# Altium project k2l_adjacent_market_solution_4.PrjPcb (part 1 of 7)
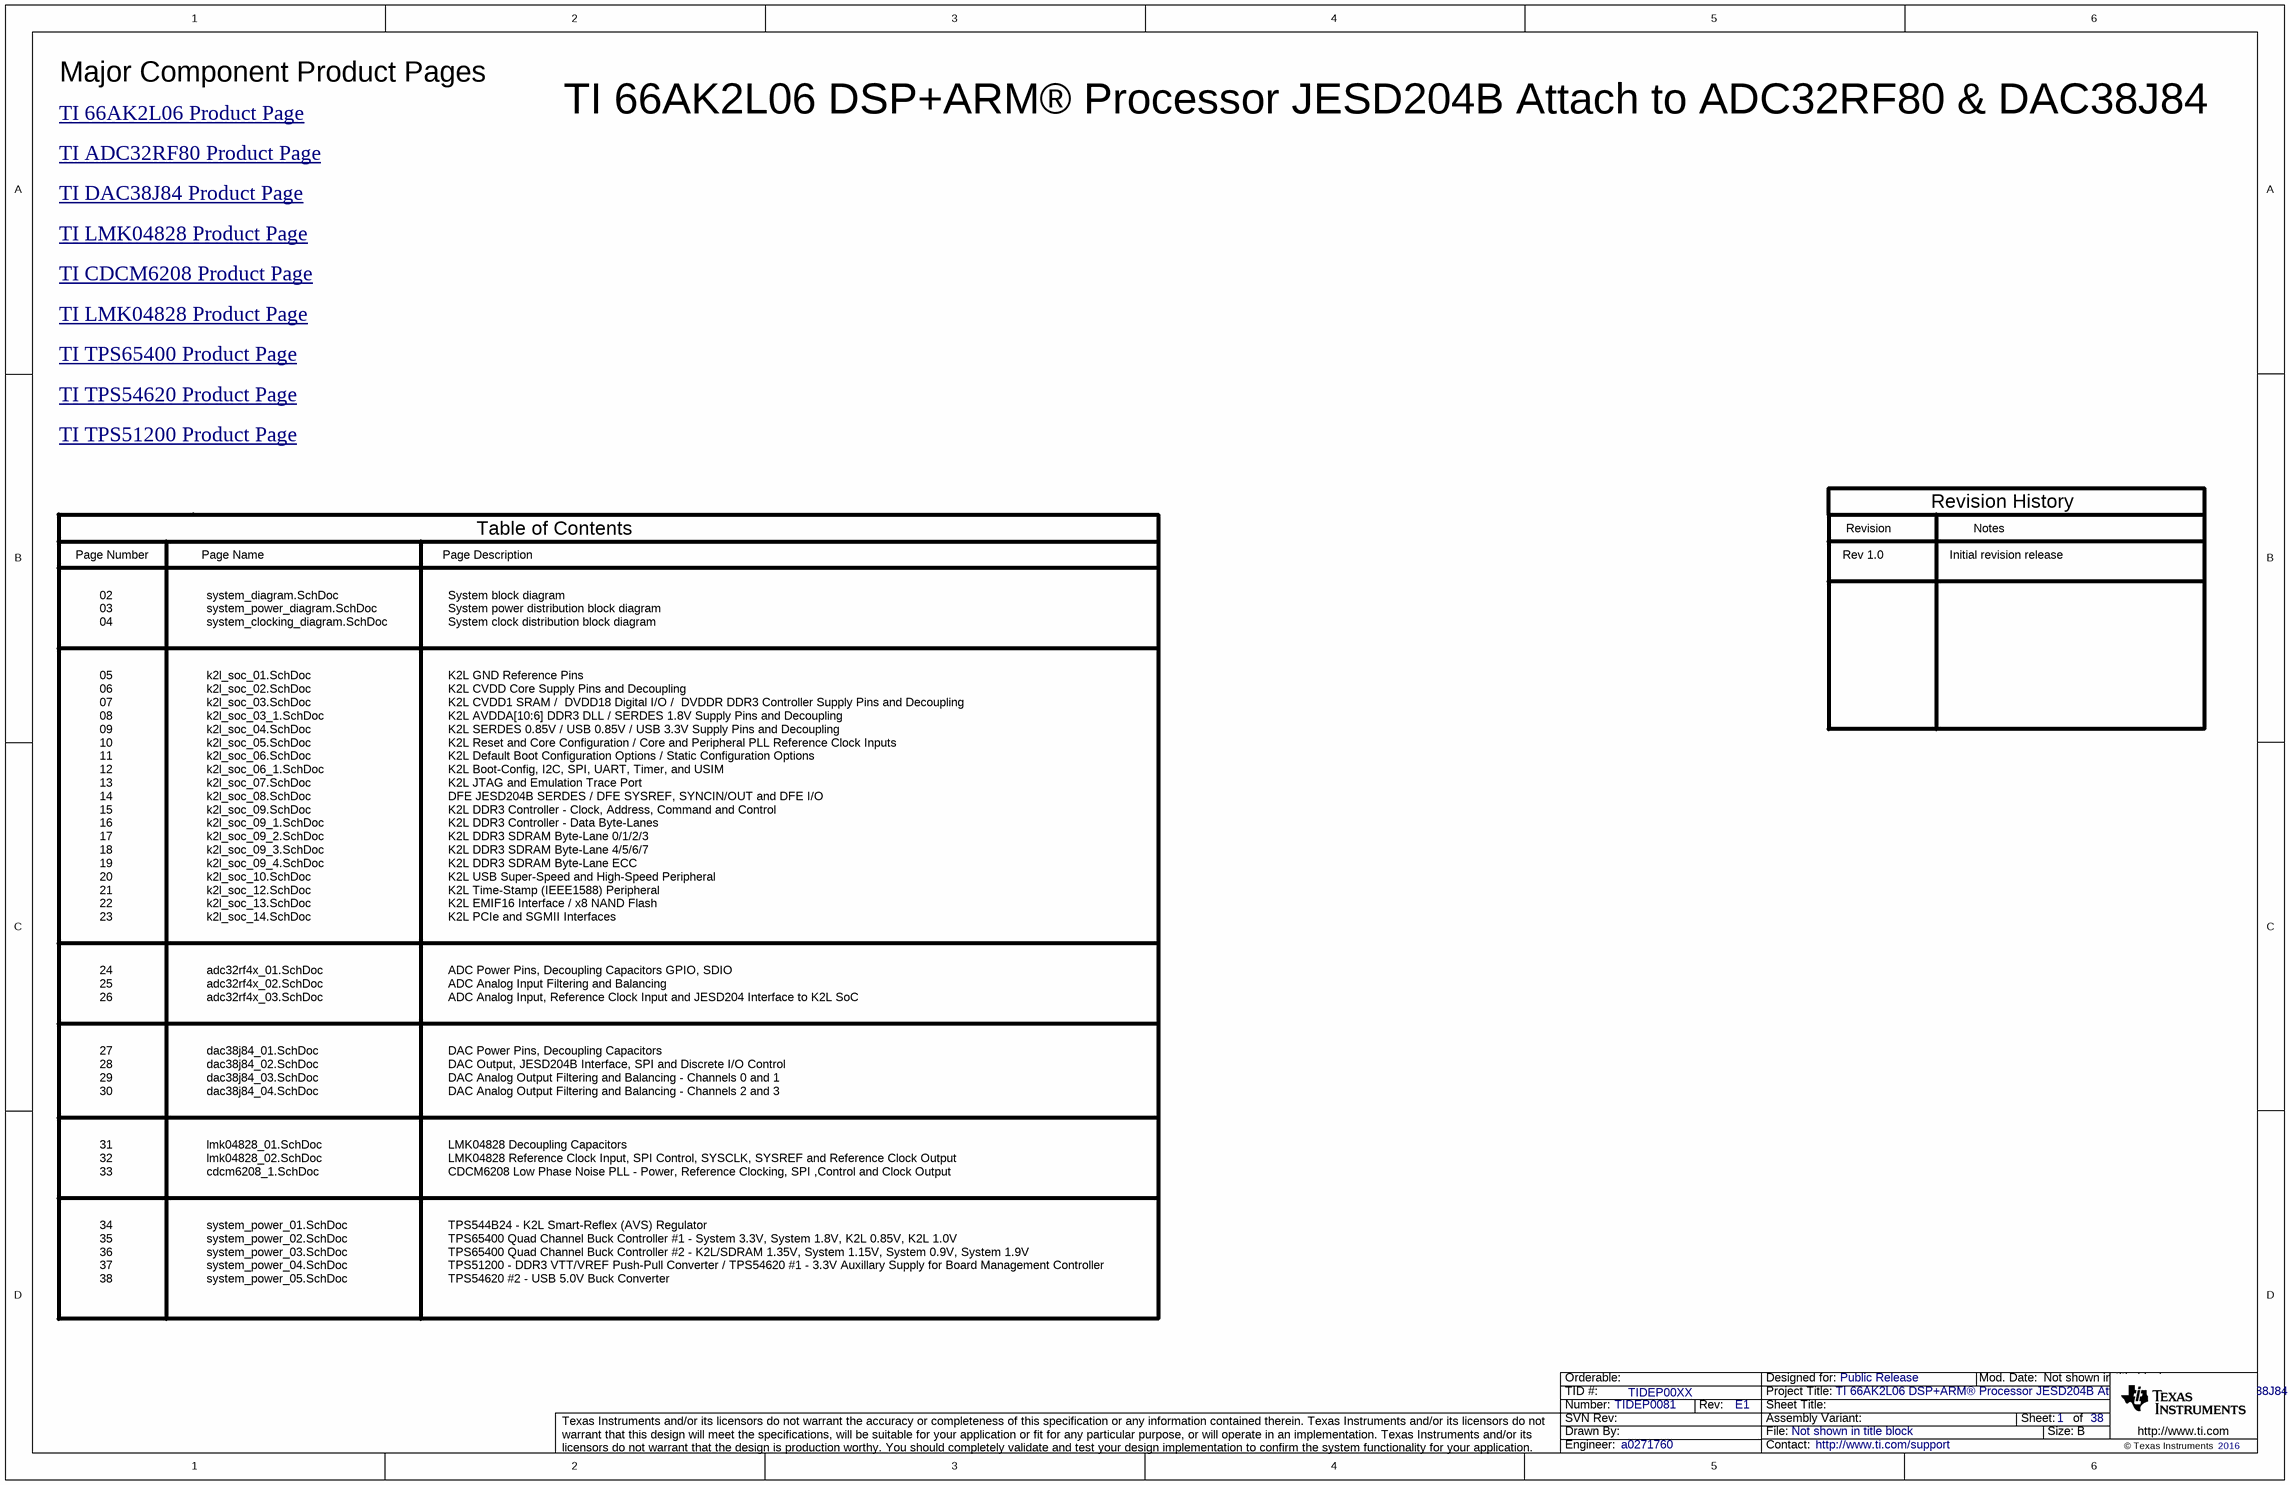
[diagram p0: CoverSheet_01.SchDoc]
TID: TIDEP00XX; TechSupport: http://www.ti.com/support; SCH_Rev: E1; PRJ_Title: TI 66AK2L06 DSP+ARM® Processor JESD204B Attach to ADC32RF80 & DAC38J84; PRJ_Number: TIDEP0081; PRJ_Engineer: a0271760; PRJ_Customer: Public Release; PCB_Rev: E1; PCB_Layout: N/A; CopyrightYear: 2016
38 sheets, 1280 parts. Net scope: flat (ports and power ports of the same name join across sheets).
Sheets:
  CoverSheet_01.SchDoc
  system_diagram.SchDoc
  system_power_diagram.SchDoc
  system_clocking_diagram.SchDoc
  k2l_soc_01.SchDoc
  k2l_soc_02.SchDoc
  k2l_soc_03.SchDoc
  k2l_soc_03_1.SchDoc
  k2l_soc_04.SchDoc
  k2l_soc_05.SchDoc
  k2l_soc_06.SchDoc
  k2l_soc_06_1.SchDoc
  k2l_soc_07.SchDoc
  k2l_soc_08.SchDoc
  k2l_soc_09.SchDoc
  k2l_soc_09_1.SchDoc
  k2l_soc_09_2.SchDoc
  k2l_soc_09_3.SchDoc
  k2l_soc_09_4.SchDoc
  k2l_soc_10.SchDoc
  k2l_soc_12.SchDoc
  k2l_soc_13.SchDoc
  k2l_soc_14.SchDoc
  adc32rf4x_01.SchDoc
  adc32rf4x_02.SchDoc
  adc32rf4x_03.SchDoc
  dac38j84_01.SchDoc
  dac38j84_02.SchDoc
  dac38j84_03.SchDoc
  dac38j84_04.SchDoc
  lmk04828_01.SchDoc
  lmk04828_02.SchDoc
  cdcm6208_1.SchDoc
  system_power_01.SchDoc
  system_power_02.SchDoc
  system_power_03.SchDoc
  system_power_04.SchDoc
  system_power_05.SchDoc

## Sheet CoverSheet_01.SchDoc
size 431 x 279 mm; Date: Not shown in title block; ApprovedBy: Not shown in title block; CheckedBy: Not shown in title block; Author: Not shown in title block; CompanyName: Not shown in title block; Engineer: Not shown in title block; Organization: Not shown in title block; Address1: Not shown in title block; Address2: Not shown in title block; Address3: Not shown in title block; Address4: Not shown in title block; DocumentNumber: 1; Revision: Use project parameter SCH_Rev; SheetNumber: 1; SheetTotal: 38; PageSetup: Record=PageOptions¦CenterHorizontal=True¦CenterVertical=True¦PrintScale=1.00¦XCorrection=1.00¦YCorrection=1.00¦PrintKind=0¦BorderSize=5000000¦LeftOffset=0¦BottomOffset=0¦Orientation=2¦PaperLength=1000¦PaperWidth=1000¦Scale=100¦PaperSource=15¦PrintQuality=600¦MediaType=1¦DitherType=10¦PaperKind=Letter¦PrintScaleMode=1

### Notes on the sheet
- Major Component Product Pages
- TI 66AK2L06 DSP+ARM® Processor JESD204B Attach to ADC32RF80 & DAC38J84
- TI 66AK2L06 Product Page <http://www.ti.com/lsds/ti/dsp/keystone_arm/66ak2lx/overview.page>
- TI ADC32RF80 Product Page <http://www.ti.com/product/ADC32RF80/description>
- TI DAC38J84 Product Page <http://www.ti.com/product/DAC38J84/description>
- TI CDCM6208 Product Page <http://www.ti.com/product/cdcm6208>
- TI LMK04828 Product Page <http://www.ti.com/product/lmk04828>
- TI TPS65400 Product Page <http://www.ti.com/product/TPS65400>
- TI TPS54620 Product Page <http://www.ti.com/product/TPS54620>
- TI TPS51200 Product Page <http://www.ti.com/product/TPS51200>
- Revision History
- Page Number
- Page Name
- Page Description
- Table of Contents
- Rev 1.0
- Revision
- Initial revision release
- Notes
- 02
- 03
- 04
- system_diagram.SchDoc
- system_power_diagram.SchDoc
- system_clocking_diagram.SchDoc
- System block diagram
- System power distribution block diagram
- System clock distribution block diagram
- 05
- 06
- 07
- k2l_soc_01.SchDoc
- k2l_soc_02.SchDoc
- k2l_soc_03.SchDoc
- K2L GND Reference Pins
- K2L CVDD Core Supply Pins and Decoupling
- K2L CVDD1 SRAM /  DVDD18 Digital I/O /  DVDDR DDR3 Controller Supply Pins and Decoupling
- 08
- 09
- 10
- 11
- 12
- k2l_soc_03_1.SchDoc
- k2l_soc_04.SchDoc
- k2l_soc_05.SchDoc
- k2l_soc_06.SchDoc
- k2l_soc_06_1.SchDoc
- K2L AVDDA[10:6] DDR3 DLL / SERDES 1.8V Supply Pins and Decoupling
- K2L SERDES 0.85V / USB 0.85V / USB 3.3V Supply Pins and Decoupling
- K2L Reset and Core Configuration / Core and Peripheral PLL Reference Clock Inputs
- K2L Default Boot Configuration Options / Static Configuration Options
- K2L Boot-Config, I2C, SPI, UART, Timer, and USIM
- 13
- 14
- 15
- 16
- 17
- k2l_soc_07.SchDoc
- k2l_soc_08.SchDoc
- k2l_soc_09.SchDoc
- k2l_soc_09_1.SchDoc
- k2l_soc_09_2.SchDoc
- K2L JTAG and Emulation Trace Port
- DFE JESD204B SERDES / DFE SYSREF, SYNCIN/OUT and DFE I/O
- K2L DDR3 Controller - Clock, Address, Command and Control
- K2L DDR3 Controller - Data Byte-Lanes
- K2L DDR3 SDRAM Byte-Lane 0/1/2/3
- 18
- 19
- 20
- 21
- 22
- k2l_soc_09_3.SchDoc
- k2l_soc_09_4.SchDoc
- k2l_soc_10.SchDoc
- k2l_soc_12.SchDoc
- k2l_soc_13.SchDoc
- K2L DDR3 SDRAM Byte-Lane 4/5/6/7
- K2L DDR3 SDRAM Byte-Lane ECC
- K2L USB Super-Speed and High-Speed Peripheral
- K2L Time-Stamp (IEEE1588) Peripheral
- K2L EMIF16 Interface / x8 NAND Flash
- 23
- 24
- k2l_soc_14.SchDoc
- adc32rf4x_01.SchDoc
- K2L PCIe and SGMII Interfaces
- ADC Power Pins, Decoupling Capacitors GPIO, SDIO
- 25
- 26
- adc32rf4x_02.SchDoc
- adc32rf4x_03.SchDoc
- ADC Analog Input Filtering and Balancing
- ADC Analog Input, Reference Clock Input and JESD204 Interface to K2L SoC
- 27
- 28
- 29
- 30
- dac38j84_01.SchDoc
- dac38j84_02.SchDoc
- dac38j84_03.SchDoc
- dac38j84_04.SchDoc
- DAC Power Pins, Decoupling Capacitors
- DAC Output, JESD204B Interface, SPI and Discrete I/O Control
- DAC Analog Output Filtering and Balancing - Channels 0 and 1
- DAC Analog Output Filtering and Balancing - Channels 2 and 3
- 31
- 32
- 33
- lmk04828_01.SchDoc
- lmk04828_02.SchDoc
- cdcm6208_1.SchDoc
- LMK04828 Decoupling Capacitors
- LMK04828 Reference Clock Input, SPI Control, SYSCLK, SYSREF and Reference Clock Output
- CDCM6208 Low Phase Noise PLL - Power, Reference Clocking, SPI ,Control and Clock Output
- 34
- 35
- system_power_01.SchDoc
- system_power_02.SchDoc
- TPS544B24 - K2L Smart-Reflex (AVS) Regulator
- TPS65400 Quad Channel Buck Controller #1 - System 3.3V, System 1.8V, K2L 0.85V, K2L 1.0V
- 36
- 37
- 38
- system_power_03.SchDoc
- system_power_04.SchDoc
- system_power_05.SchDoc
- TPS65400 Quad Channel Buck Controller #2 - K2L/SDRAM 1.35V, System 1.15V, System 0.9V, System 1.9V
- TPS51200 - DDR3 VTT/VREF Push-Pull Converter / TPS54620 #1 - 3.3V Auxillary Supply for Board Management Controller
- TPS54620 #2 - USB 5.0V Buck Converter

## Sheet system_diagram.SchDoc
size 431 x 279 mm; Date: Not shown in title block; ApprovedBy: Not shown in title block; CheckedBy: Not shown in title block; Author: Not shown in title block; CompanyName: Not shown in title block; DrawnBy: a0271760; Engineer: a0271760; Organization: Not shown in title block; Address1: Not shown in title block; Address2: Not shown in title block; Address3: Not shown in title block; Address4: Not shown in title block; DocumentNumber: 2; Revision: Use project parameter SCH_Rev; SheetNumber: 2; SheetTotal: 38; PageSetup: Record=PageOptions¦CenterHorizontal=True¦CenterVertical=True¦PrintScale=1.00¦XCorrection=1.00¦YCorrection=1.00¦PrintKind=0¦BorderSize=5000000¦LeftOffset=0¦BottomOffset=0¦Orientation=2¦PaperLength=1000¦PaperWidth=1000¦Scale=100¦PaperSource=15¦PrintQuality=600¦MediaType=1¦DitherType=10¦PaperKind=Letter¦PrintScaleMode=1
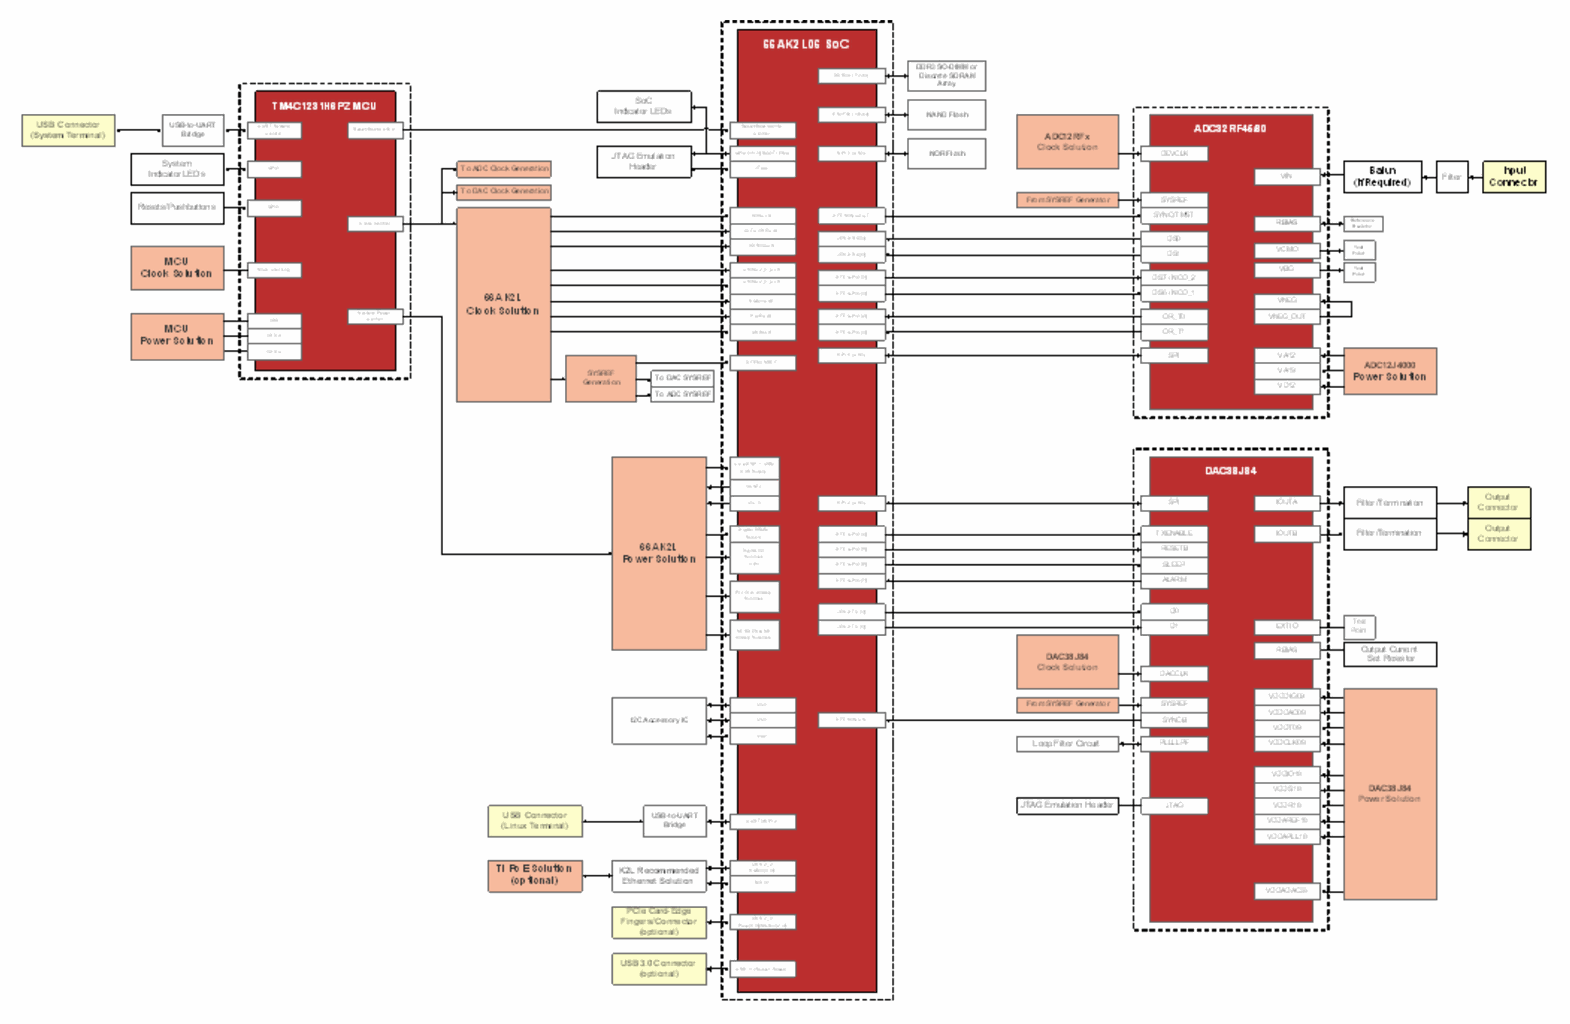
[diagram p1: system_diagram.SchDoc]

## Sheet system_power_diagram.SchDoc
size 431 x 279 mm; Date: Not shown in title block; ApprovedBy: Not shown in title block; CheckedBy: Not shown in title block; Author: Not shown in title block; CompanyName: Not shown in title block; Engineer: Not shown in title block; Organization: Not shown in title block; Address1: Not shown in title block; Address2: Not shown in title block; Address3: Not shown in title block; Address4: Not shown in title block; DocumentNumber: 3; Revision: Use project parameter SCH_Rev; SheetNumber: 3; SheetTotal: 38; PageSetup: Record=PageOptions¦CenterHorizontal=True¦CenterVertical=True¦PrintScale=1.00¦XCorrection=1.00¦YCorrection=1.00¦PrintKind=0¦BorderSize=5000000¦LeftOffset=0¦BottomOffset=0¦Orientation=2¦PaperLength=1000¦PaperWidth=1000¦Scale=100¦PaperSource=15¦PrintQuality=600¦MediaType=1¦DitherType=10¦PaperKind=Letter¦PrintScaleMode=1
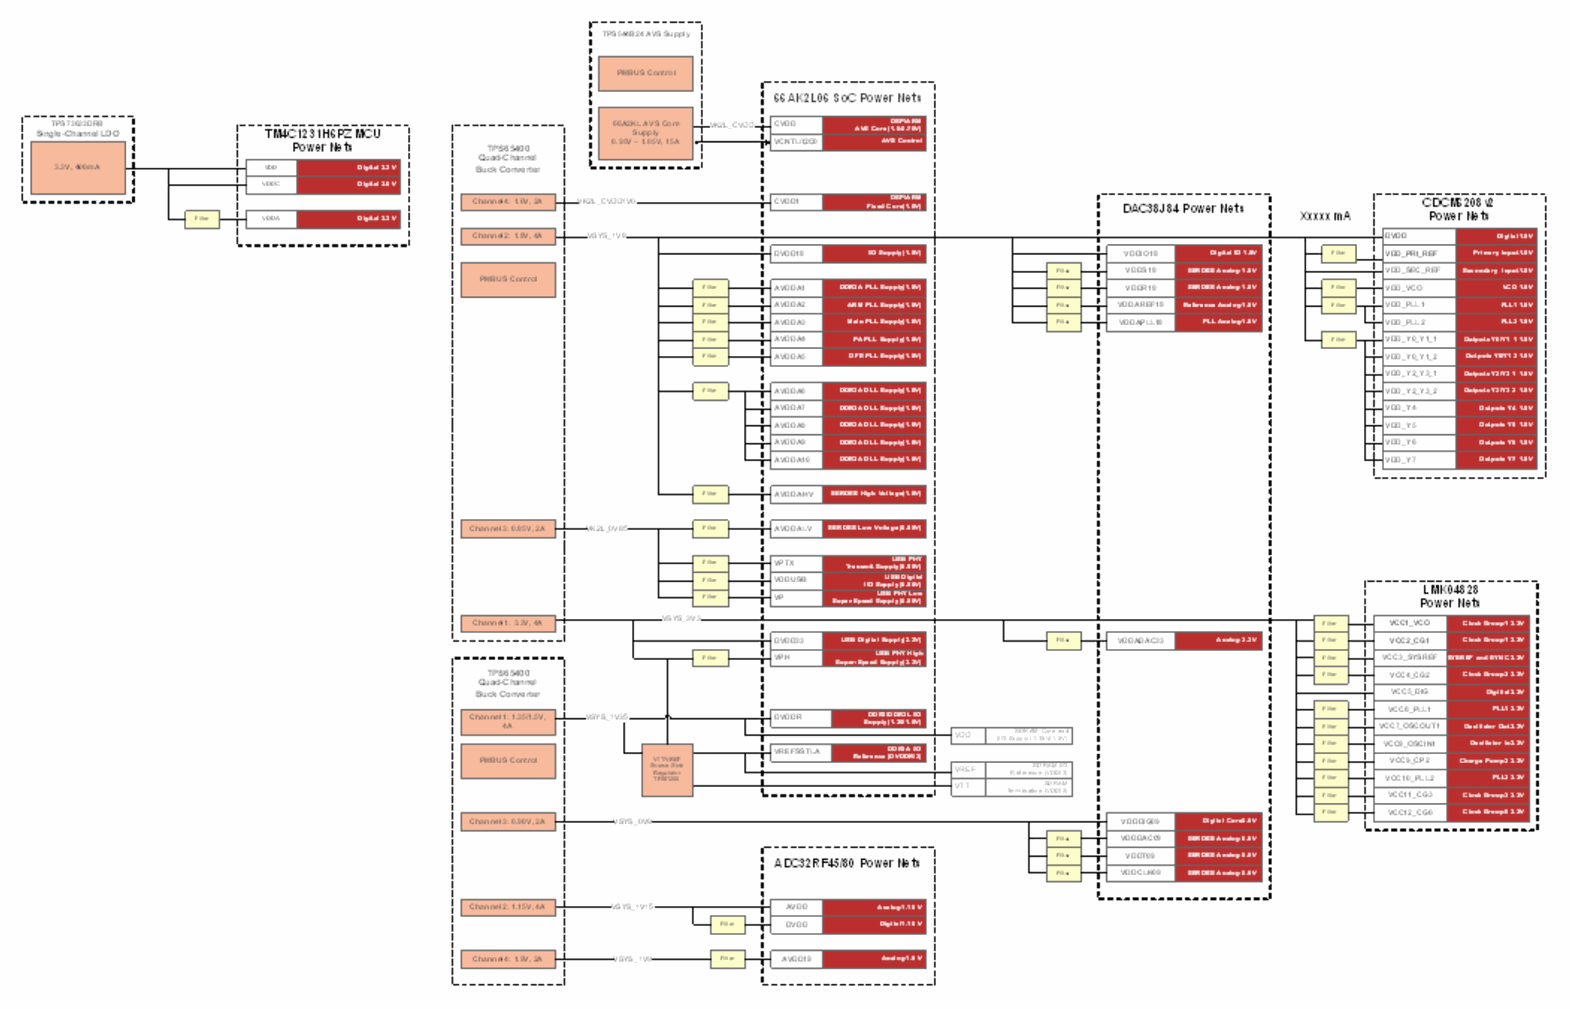
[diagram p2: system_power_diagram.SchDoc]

## Sheet system_clocking_diagram.SchDoc
size 431 x 279 mm; Date: Not shown in title block; ApprovedBy: Not shown in title block; CheckedBy: Not shown in title block; Author: Not shown in title block; CompanyName: Not shown in title block; Engineer: Not shown in title block; Organization: Not shown in title block; Address1: Not shown in title block; Address2: Not shown in title block; Address3: Not shown in title block; Address4: Not shown in title block; DocumentNumber: 4; Revision: Use project parameter SCH_Rev; SheetNumber: 4; SheetTotal: 38; PageSetup: Record=PageOptions¦CenterHorizontal=True¦CenterVertical=True¦PrintScale=1.00¦XCorrection=1.00¦YCorrection=1.00¦PrintKind=0¦BorderSize=5000000¦LeftOffset=0¦BottomOffset=0¦Orientation=2¦PaperLength=1000¦PaperWidth=1000¦Scale=100¦PaperSource=15¦PrintQuality=600¦MediaType=1¦DitherType=10¦PaperKind=Letter¦PrintScaleMode=1
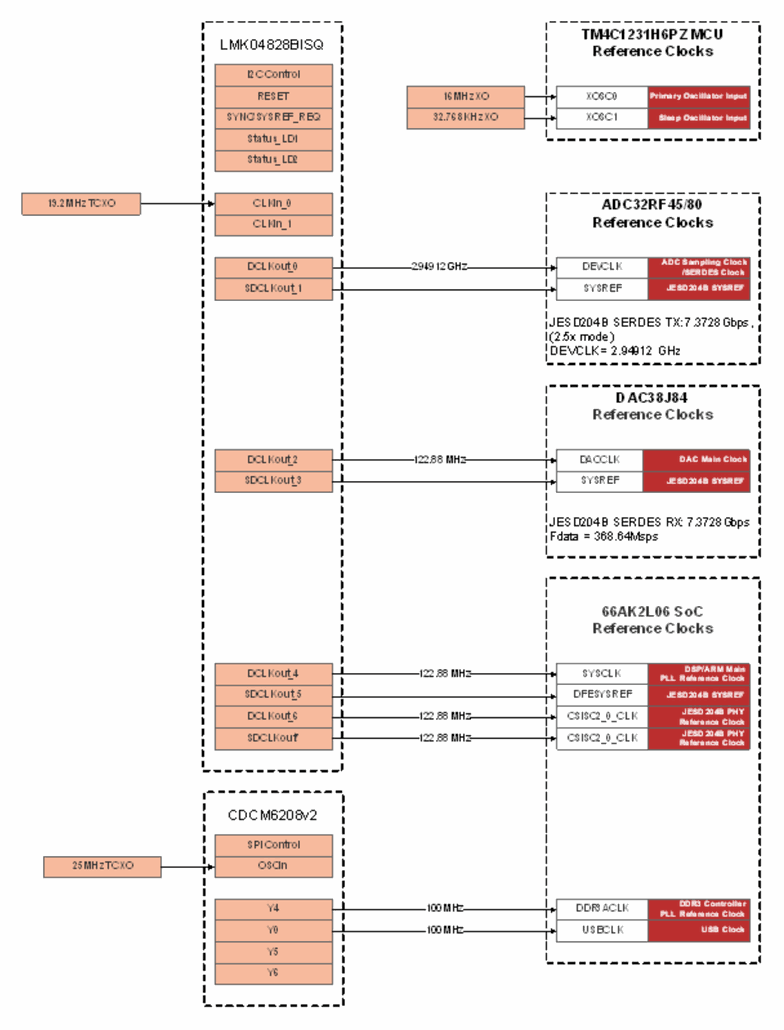
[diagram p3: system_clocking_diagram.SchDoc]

## Sheet k2l_soc_01.SchDoc
size 431 x 279 mm; Date: Not shown in title block; ApprovedBy: Not shown in title block; CheckedBy: Not shown in title block; Author: Not shown in title block; CompanyName: Not shown in title block; Engineer: Not shown in title block; Organization: Not shown in title block; Address1: Not shown in title block; Address2: Not shown in title block; Address3: Not shown in title block; Address4: Not shown in title block; DocumentNumber: 5; Revision: Use project parameter SCH_Rev; SheetNumber: 5; SheetTotal: 38; PageSetup: Record=PageOptions¦CenterHorizontal=True¦CenterVertical=True¦PrintScale=1.00¦XCorrection=1.00¦YCorrection=1.00¦PrintKind=0¦BorderSize=5000000¦LeftOffset=0¦BottomOffset=0¦Orientation=2¦PaperLength=1000¦PaperWidth=1000¦Scale=100¦PaperSource=15¦PrintQuality=600¦MediaType=1¦DitherType=10¦PaperKind=Letter¦PrintScaleMode=1
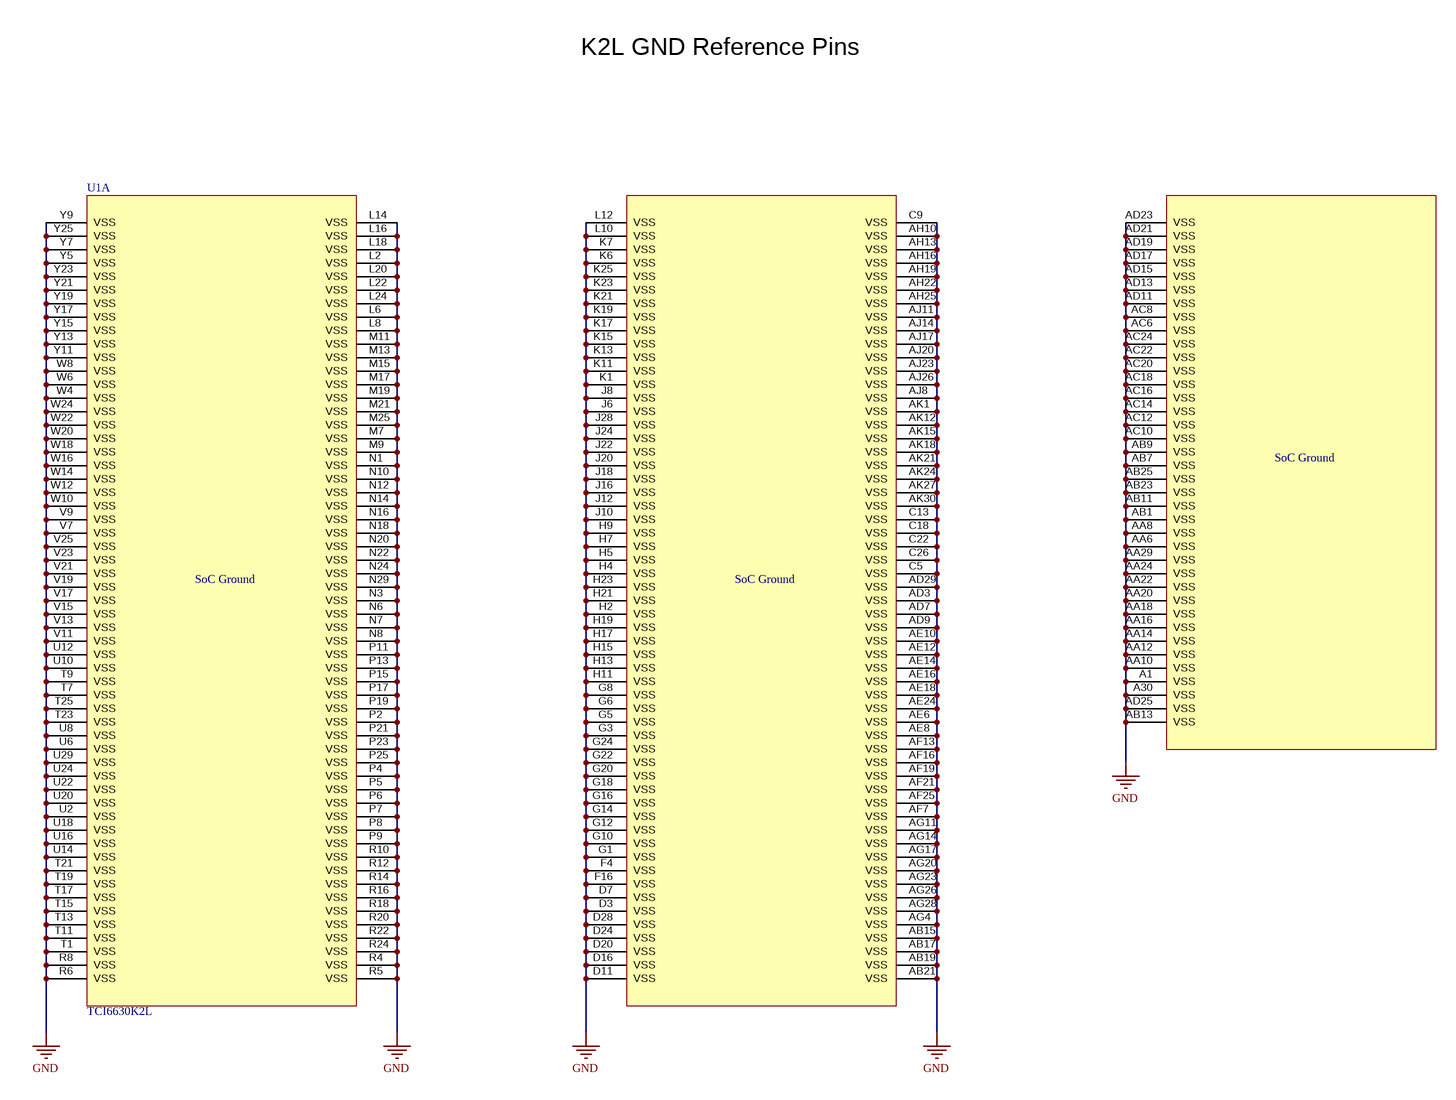
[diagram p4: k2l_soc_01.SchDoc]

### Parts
U1  TCI6630K2L  [BGA900C80P30X30_2500X2500X355]  (part A of 24)

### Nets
GND: U1.A1(VSS) U1.A30(VSS) U1.AA6(VSS) U1.AA8(VSS) U1.AA10(VSS) U1.AA12(VSS) U1.AA14(VSS) U1.AA16(VSS) U1.AA18(VSS) U1.AA20(VSS) U1.AA22(VSS) U1.AA24(VSS) U1.AA29(VSS) U1.AB1(VSS) U1.AB7(VSS) U1.AB9(VSS) U1.AB11(VSS) U1.AB13(VSS) U1.AB15(VSS) U1.AB17(VSS) U1.AB19(VSS) U1.AB21(VSS) U1.AB23(VSS) U1.AB25(VSS) U1.AC6(VSS) U1.AC8(VSS) U1.AC10(VSS) U1.AC12(VSS) U1.AC14(VSS) U1.AC16(VSS) U1.AC18(VSS) U1.AC20(VSS) U1.AC22(VSS) U1.AC24(VSS) U1.AD3(VSS) U1.AD7(VSS) U1.AD9(VSS) U1.AD11(VSS) U1.AD13(VSS) U1.AD15(VSS) U1.AD17(VSS) U1.AD19(VSS) U1.AD21(VSS) U1.AD23(VSS) U1.AD25(VSS) U1.AD29(VSS) U1.AE6(VSS) U1.AE8(VSS) U1.AE10(VSS) U1.AE12(VSS) U1.AE14(VSS) U1.AE16(VSS) U1.AE18(VSS) U1.AE24(VSS) U1.AF7(VSS) U1.AF13(VSS) U1.AF16(VSS) U1.AF19(VSS) U1.AF21(VSS) U1.AF25(VSS) U1.AG4(VSS) U1.AG11(VSS) U1.AG14(VSS) U1.AG17(VSS) U1.AG20(VSS) U1.AG23(VSS) U1.AG26(VSS) U1.AG28(VSS) U1.AH10(VSS) U1.AH13(VSS) U1.AH16(VSS) U1.AH19(VSS) U1.AH22(VSS) U1.AH25(VSS) U1.AJ8(VSS) U1.AJ11(VSS) U1.AJ14(VSS) U1.AJ17(VSS) U1.AJ20(VSS) U1.AJ23(VSS) U1.AJ26(VSS) U1.AK1(VSS) U1.AK12(VSS) U1.AK15(VSS) U1.AK18(VSS) U1.AK21(VSS) U1.AK24(VSS) U1.AK27(VSS) U1.AK30(VSS) U1.C5(VSS) U1.C9(VSS) U1.C13(VSS) U1.C18(VSS) U1.C22(VSS) U1.C26(VSS) U1.D3(VSS) U1.D7(VSS) U1.D11(VSS) U1.D16(VSS) U1.D20(VSS) U1.D24(VSS) U1.D28(VSS) U1.F4(VSS) U1.F16(VSS) U1.G1(VSS) U1.G3(VSS) U1.G5(VSS) U1.G6(VSS) U1.G8(VSS) U1.G10(VSS) U1.G12(VSS) U1.G14(VSS) U1.G16(VSS) U1.G18(VSS) U1.G20(VSS) U1.G22(VSS) U1.G24(VSS) U1.H2(VSS) U1.H4(VSS) U1.H5(VSS) U1.H7(VSS) U1.H9(VSS) U1.H11(VSS) U1.H13(VSS) U1.H15(VSS) U1.H17(VSS) U1.H19(VSS) U1.H21(VSS) U1.H23(VSS) U1.J6(VSS) U1.J8(VSS) U1.J10(VSS) U1.J12(VSS) U1.J16(VSS) U1.J18(VSS) U1.J20(VSS) U1.J22(VSS) U1.J24(VSS) U1.J28(VSS) U1.K1(VSS) U1.K6(VSS) U1.K7(VSS) U1.K11(VSS) U1.K13(VSS) U1.K15(VSS) U1.K17(VSS) U1.K19(VSS) U1.K21(VSS) U1.K23(VSS) U1.K25(VSS) U1.L2(VSS) U1.L6(VSS) U1.L8(VSS) U1.L10(VSS) U1.L12(VSS) U1.L14(VSS) U1.L16(VSS) U1.L18(VSS) U1.L20(VSS) U1.L22(VSS) U1.L24(VSS) U1.M7(VSS) U1.M9(VSS) U1.M11(VSS) U1.M13(VSS) U1.M15(VSS) U1.M17(VSS) U1.M19(VSS) U1.M21(VSS) U1.M25(VSS) U1.N1(VSS) U1.N3(VSS) U1.N6(VSS) U1.N7(VSS) U1.N8(VSS) U1.N10(VSS) U1.N12(VSS) U1.N14(VSS) U1.N16(VSS) U1.N18(VSS) U1.N20(VSS) U1.N22(VSS) U1.N24(VSS) U1.N29(VSS) U1.P2(VSS) U1.P4(VSS) U1.P5(VSS) U1.P6(VSS) U1.P7(VSS) U1.P8(VSS) U1.P9(VSS) U1.P11(VSS) U1.P13(VSS) U1.P15(VSS) U1.P17(VSS) U1.P19(VSS) U1.P21(VSS) U1.P23(VSS) U1.P25(VSS) U1.R4(VSS) U1.R5(VSS) U1.R6(VSS) U1.R8(VSS) U1.R10(VSS) U1.R12(VSS) U1.R14(VSS) U1.R16(VSS) U1.R18(VSS) U1.R20(VSS) U1.R22(VSS) U1.R24(VSS) U1.T1(VSS) U1.T7(VSS) U1.T9(VSS) U1.T11(VSS) U1.T13(VSS) U1.T15(VSS) U1.T17(VSS) U1.T19(VSS) U1.T21(VSS) U1.T23(VSS) U1.T25(VSS) U1.U2(VSS) U1.U6(VSS) U1.U8(VSS) U1.U10(VSS) U1.U12(VSS) U1.U14(VSS) U1.U16(VSS) U1.U18(VSS) U1.U20(VSS) U1.U22(VSS) U1.U24(VSS) U1.U29(VSS) U1.V7(VSS) U1.V9(VSS) U1.V11(VSS) U1.V13(VSS) U1.V15(VSS) U1.V17(VSS) U1.V19(VSS) U1.V21(VSS) U1.V23(VSS) U1.V25(VSS) U1.W4(VSS) U1.W6(VSS) U1.W8(VSS) U1.W10(VSS) U1.W12(VSS) U1.W14(VSS) U1.W16(VSS) U1.W18(VSS) U1.W20(VSS) U1.W22(VSS) U1.W24(VSS) U1.Y5(VSS) U1.Y7(VSS) U1.Y9(VSS) U1.Y11(VSS) U1.Y13(VSS) U1.Y15(VSS) U1.Y17(VSS) U1.Y19(VSS) U1.Y21(VSS) U1.Y23(VSS) U1.Y25(VSS)  [project net DAC_OUT0N_T1]

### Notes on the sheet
- K2L GND Reference Pins

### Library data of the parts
U1 = lamarr_soc_TCI6630K2L: Smallcell Baseband Processor with 4 C66x DSP Cores / 2 ARM A15 Cores / JESD / CPRI...etc

## Sheet k2l_soc_02.SchDoc
size 431 x 279 mm; Date: Not shown in title block; ApprovedBy: Not shown in title block; CheckedBy: Not shown in title block; Author: Not shown in title block; CompanyName: Not shown in title block; Engineer: Not shown in title block; Organization: Not shown in title block; Address1: Not shown in title block; Address2: Not shown in title block; Address3: Not shown in title block; Address4: Not shown in title block; DocumentNumber: 6; Revision: Use project parameter SCH_Rev; SheetNumber: 6; SheetTotal: 38; PageSetup: Record=PageOptions¦CenterHorizontal=True¦CenterVertical=True¦PrintScale=1.00¦XCorrection=1.00¦YCorrection=1.00¦PrintKind=0¦BorderSize=5000000¦LeftOffset=0¦BottomOffset=0¦Orientation=2¦PaperLength=1000¦PaperWidth=1000¦Scale=100¦PaperSource=15¦PrintQuality=600¦MediaType=1¦DitherType=10¦PaperKind=Letter¦PrintScaleMode=1
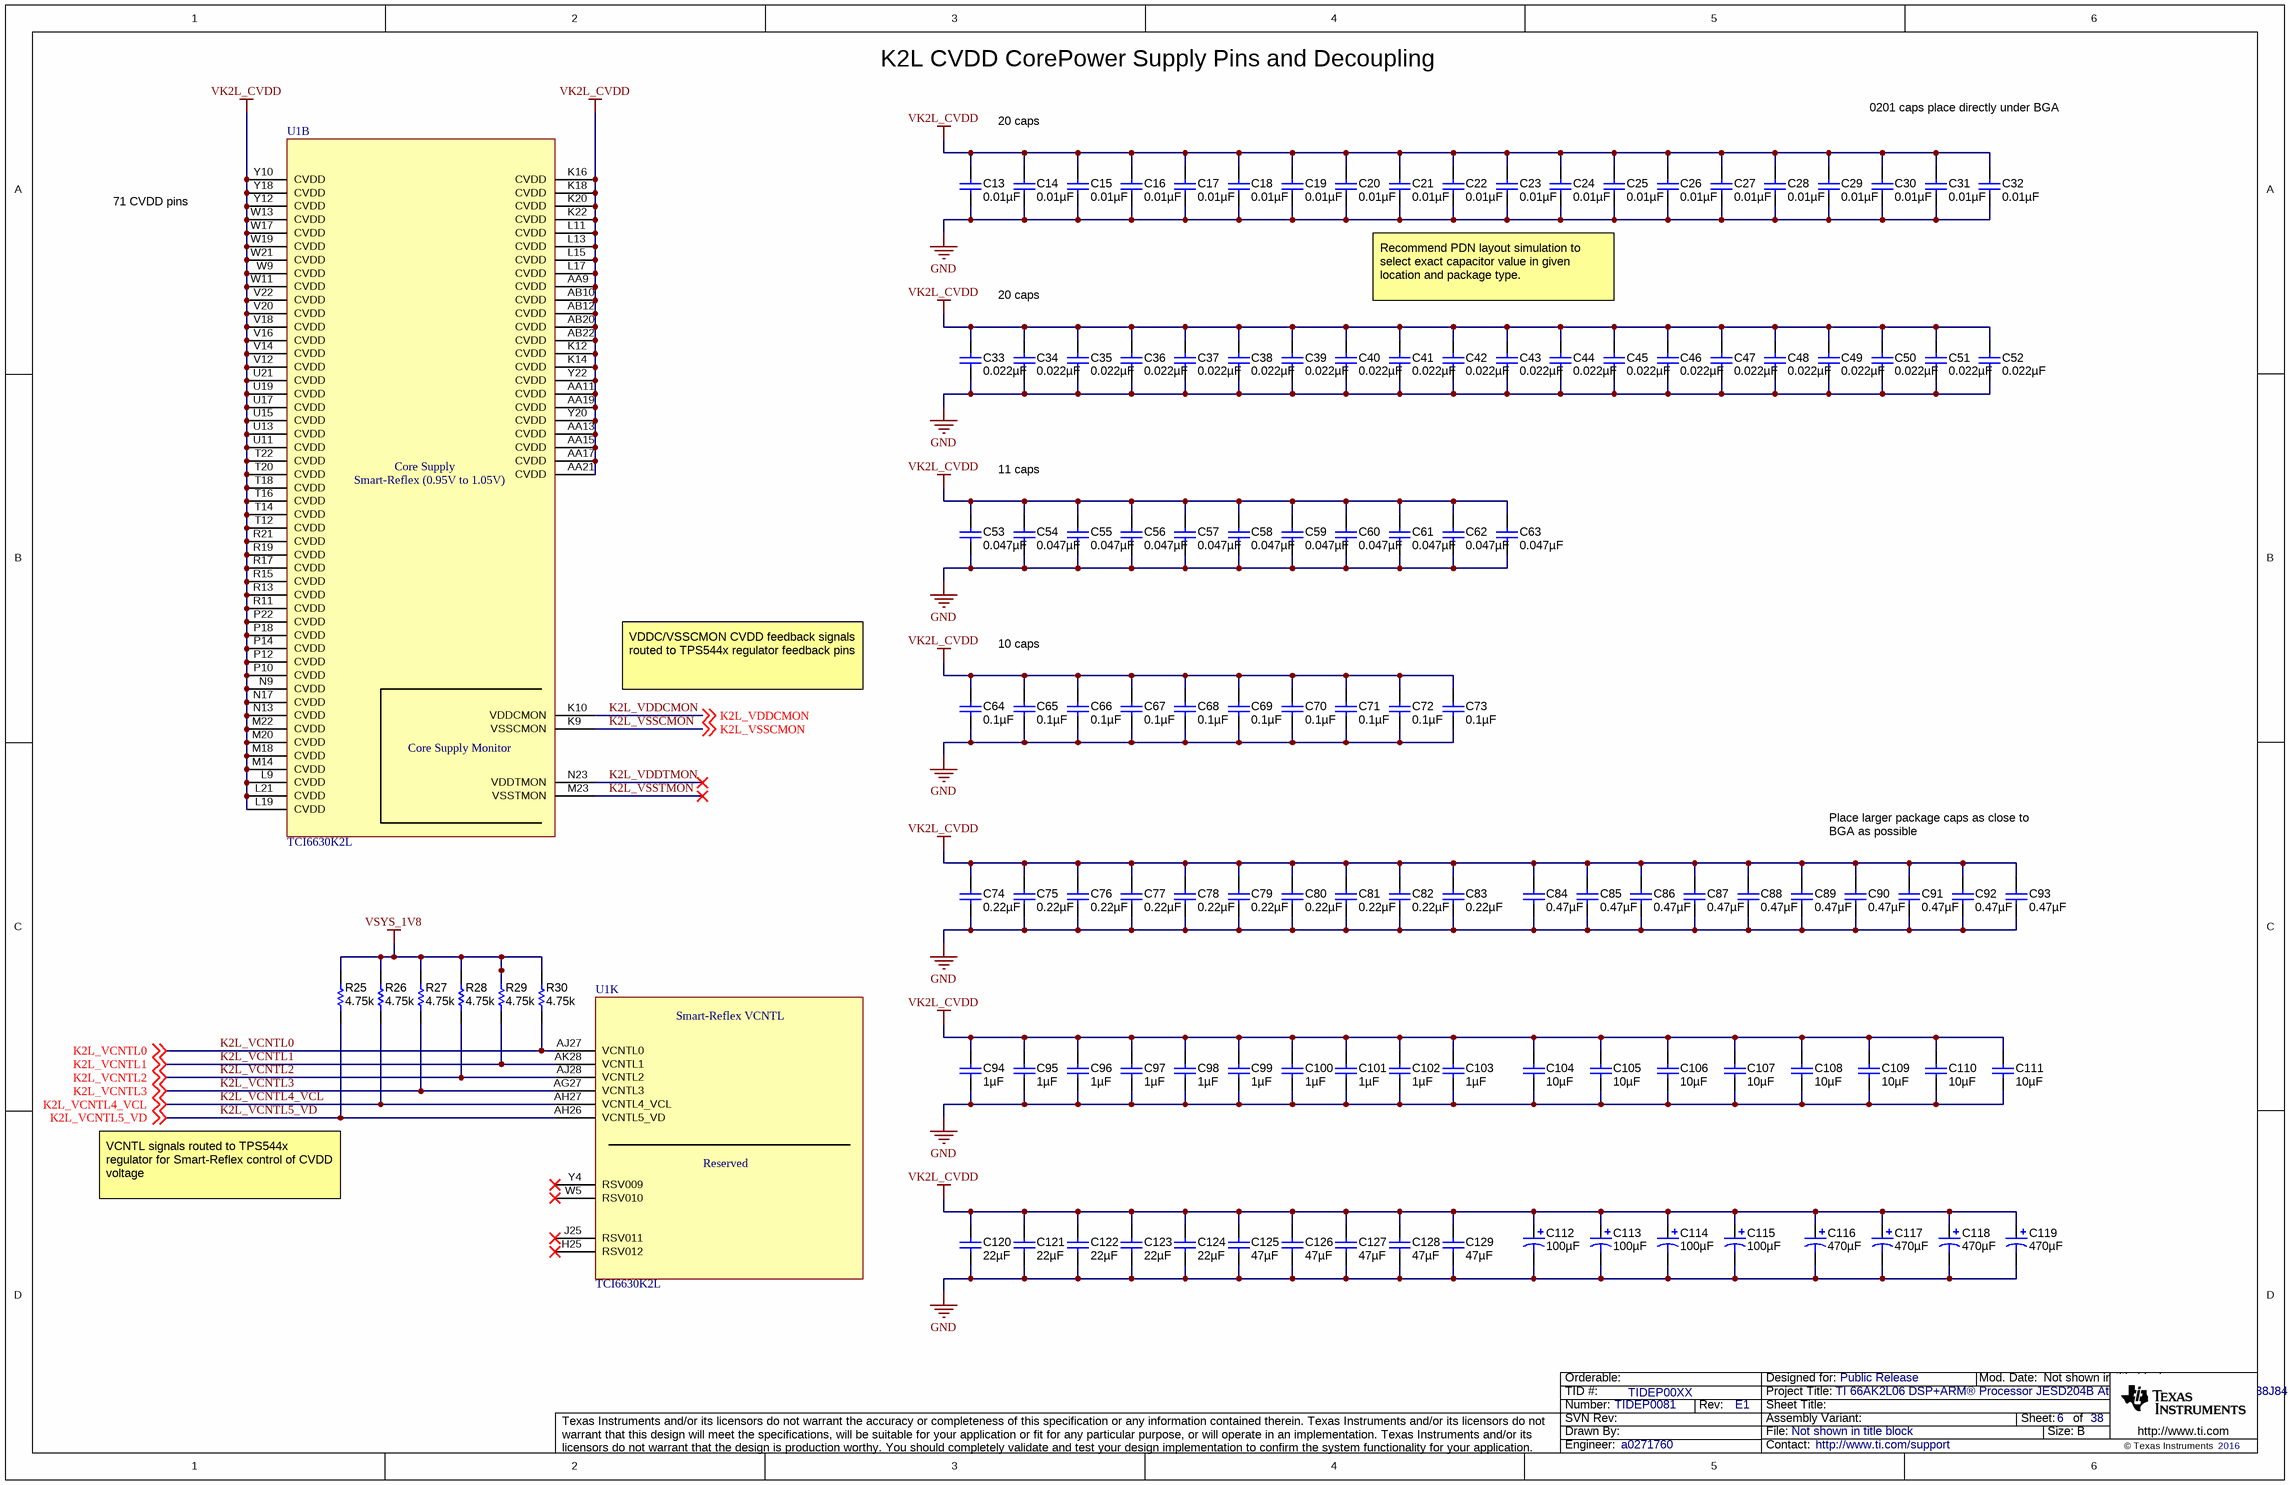
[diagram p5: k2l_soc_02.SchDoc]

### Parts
C13  ValueDisplayed: 0.01µF  [0201]  (hidden comment: GRM033R70J103KA01D)
C14  ValueDisplayed: 0.01µF  [0201]  (hidden comment: GRM033R70J103KA01D)
C15  ValueDisplayed: 0.01µF  [0201]  (hidden comment: GRM033R70J103KA01D)
C16  ValueDisplayed: 0.01µF  [0201]  (hidden comment: GRM033R70J103KA01D)
C17  ValueDisplayed: 0.01µF  [0201]  (hidden comment: GRM033R70J103KA01D)
C18  ValueDisplayed: 0.01µF  [0201]  (hidden comment: GRM033R70J103KA01D)
C19  ValueDisplayed: 0.01µF  [0201]  (hidden comment: GRM033R70J103KA01D)
C20  ValueDisplayed: 0.01µF  [0201]  (hidden comment: GRM033R70J103KA01D)
C21  ValueDisplayed: 0.01µF  [0201]  (hidden comment: GRM033R70J103KA01D)
C22  ValueDisplayed: 0.01µF  [0201]  (hidden comment: GRM033R70J103KA01D)
C23  ValueDisplayed: 0.01µF  [0201]  (hidden comment: GRM033R70J103KA01D)
C24  ValueDisplayed: 0.01µF  [0201]  (hidden comment: GRM033R70J103KA01D)
C25  ValueDisplayed: 0.01µF  [0201]  (hidden comment: GRM033R70J103KA01D)
C26  ValueDisplayed: 0.01µF  [0201]  (hidden comment: GRM033R70J103KA01D)
C27  ValueDisplayed: 0.01µF  [0201]  (hidden comment: GRM033R70J103KA01D)
C28  ValueDisplayed: 0.01µF  [0201]  (hidden comment: GRM033R70J103KA01D)
C29  ValueDisplayed: 0.01µF  [0201]  (hidden comment: GRM033R70J103KA01D)
C30  ValueDisplayed: 0.01µF  [0201]  (hidden comment: GRM033R70J103KA01D)
C31  ValueDisplayed: 0.01µF  [0201]  (hidden comment: GRM033R70J103KA01D)
C32  ValueDisplayed: 0.01µF  [0201]  (hidden comment: GRM033R70J103KA01D)
C33  ValueDisplayed: 0.022µF  [0201]  (hidden comment: GRM033R60J223KE01D)
C34  ValueDisplayed: 0.022µF  [0201]  (hidden comment: GRM033R60J223KE01D)
C35  ValueDisplayed: 0.022µF  [0201]  (hidden comment: GRM033R60J223KE01D)
C36  ValueDisplayed: 0.022µF  [0201]  (hidden comment: GRM033R60J223KE01D)
C37  ValueDisplayed: 0.022µF  [0201]  (hidden comment: GRM033R60J223KE01D)
C38  ValueDisplayed: 0.022µF  [0201]  (hidden comment: GRM033R60J223KE01D)
C39  ValueDisplayed: 0.022µF  [0201]  (hidden comment: GRM033R60J223KE01D)
C40  ValueDisplayed: 0.022µF  [0201]  (hidden comment: GRM033R60J223KE01D)
C41  ValueDisplayed: 0.022µF  [0201]  (hidden comment: GRM033R60J223KE01D)
C42  ValueDisplayed: 0.022µF  [0201]  (hidden comment: GRM033R60J223KE01D)
C43  ValueDisplayed: 0.022µF  [0201]  (hidden comment: GRM033R60J223KE01D)
C44  ValueDisplayed: 0.022µF  [0201]  (hidden comment: GRM033R60J223KE01D)
C45  ValueDisplayed: 0.022µF  [0201]  (hidden comment: GRM033R60J223KE01D)
C46  ValueDisplayed: 0.022µF  [0201]  (hidden comment: GRM033R60J223KE01D)
C47  ValueDisplayed: 0.022µF  [0201]  (hidden comment: GRM033R60J223KE01D)
C48  ValueDisplayed: 0.022µF  [0201]  (hidden comment: GRM033R60J223KE01D)
C49  ValueDisplayed: 0.022µF  [0201]  (hidden comment: GRM033R60J223KE01D)
C50  ValueDisplayed: 0.022µF  [0201]  (hidden comment: GRM033R60J223KE01D)
C51  ValueDisplayed: 0.022µF  [0201]  (hidden comment: GRM033R60J223KE01D)
C52  ValueDisplayed: 0.022µF  [0201]  (hidden comment: GRM033R60J223KE01D)
C53  ValueDisplayed: 0.047µF  [0201]  (hidden comment: GRM033R60J473KE19D)
C54  ValueDisplayed: 0.047µF  [0201]  (hidden comment: GRM033R60J473KE19D)
C55  ValueDisplayed: 0.047µF  [0201]  (hidden comment: GRM033R60J473KE19D)
C56  ValueDisplayed: 0.047µF  [0201]  (hidden comment: GRM033R60J473KE19D)
C57  ValueDisplayed: 0.047µF  [0201]  (hidden comment: GRM033R60J473KE19D)
C58  ValueDisplayed: 0.047µF  [0201]  (hidden comment: GRM033R60J473KE19D)
C59  ValueDisplayed: 0.047µF  [0201]  (hidden comment: GRM033R60J473KE19D)
C60  ValueDisplayed: 0.047µF  [0201]  (hidden comment: GRM033R60J473KE19D)
C61  ValueDisplayed: 0.047µF  [0201]  (hidden comment: GRM033R60J473KE19D)
C62  ValueDisplayed: 0.047µF  [0201]  (hidden comment: GRM033R60J473KE19D)
C63  ValueDisplayed: 0.047µF  [0201]  (hidden comment: GRM033R60J473KE19D)
C64  ValueDisplayed: 0.1µF  [0201_033]  (hidden comment: GRM033R60J104KE19D)
C65  ValueDisplayed: 0.1µF  [0201_033]  (hidden comment: GRM033R60J104KE19D)
C66  ValueDisplayed: 0.1µF  [0201_033]  (hidden comment: GRM033R60J104KE19D)
C67  ValueDisplayed: 0.1µF  [0201_033]  (hidden comment: GRM033R60J104KE19D)
C68  ValueDisplayed: 0.1µF  [0201_033]  (hidden comment: GRM033R60J104KE19D)
C69  ValueDisplayed: 0.1µF  [0201_033]  (hidden comment: GRM033R60J104KE19D)
C70  ValueDisplayed: 0.1µF  [0201_033]  (hidden comment: GRM033R60J104KE19D)
C71  ValueDisplayed: 0.1µF  [0201_033]  (hidden comment: GRM033R60J104KE19D)
C72  ValueDisplayed: 0.1µF  [0201_033]  (hidden comment: GRM033R60J104KE19D)
C73  ValueDisplayed: 0.1µF  [0201_033]  (hidden comment: GRM033R60J104KE19D)
C74  ValueDisplayed: 0.22µF  [0603]  (hidden comment: GRM188R61A224KA01D)
C75  ValueDisplayed: 0.22µF  [0603]  (hidden comment: GRM188R61A224KA01D)
C76  ValueDisplayed: 0.22µF  [0603]  (hidden comment: GRM188R61A224KA01D)
C77  ValueDisplayed: 0.22µF  [0603]  (hidden comment: GRM188R61A224KA01D)
C78  ValueDisplayed: 0.22µF  [0603]  (hidden comment: GRM188R61A224KA01D)
C79  ValueDisplayed: 0.22µF  [0603]  (hidden comment: GRM188R61A224KA01D)
C80  ValueDisplayed: 0.22µF  [0603]  (hidden comment: GRM188R61A224KA01D)
C81  ValueDisplayed: 0.22µF  [0603]  (hidden comment: GRM188R61A224KA01D)
C82  ValueDisplayed: 0.22µF  [0603]  (hidden comment: GRM188R61A224KA01D)
C83  ValueDisplayed: 0.22µF  [0603]  (hidden comment: GRM188R61A224KA01D)
C84  ValueDisplayed: 0.47µF  [0603]  (hidden comment: GRM188R61A474KA61D)
C85  ValueDisplayed: 0.47µF  [0603]  (hidden comment: GRM188R61A474KA61D)
C86  ValueDisplayed: 0.47µF  [0603]  (hidden comment: GRM188R61A474KA61D)
C87  ValueDisplayed: 0.47µF  [0603]  (hidden comment: GRM188R61A474KA61D)
C88  ValueDisplayed: 0.47µF  [0603]  (hidden comment: GRM188R61A474KA61D)
C89  ValueDisplayed: 0.47µF  [0603]  (hidden comment: GRM188R61A474KA61D)
C90  ValueDisplayed: 0.47µF  [0603]  (hidden comment: GRM188R61A474KA61D)
C91  ValueDisplayed: 0.47µF  [0603]  (hidden comment: GRM188R61A474KA61D)
C92  ValueDisplayed: 0.47µF  [0603]  (hidden comment: GRM188R61A474KA61D)
C93  ValueDisplayed: 0.47µF  [0603]  (hidden comment: GRM188R61A474KA61D)
C94  ValueDisplayed: 1µF  [0603]  (hidden comment: GRM188R70J105KA01D)
C95  ValueDisplayed: 1µF  [0603]  (hidden comment: GRM188R70J105KA01D)
C96  ValueDisplayed: 1µF  [0603]  (hidden comment: GRM188R70J105KA01D)
C97  ValueDisplayed: 1µF  [0603]  (hidden comment: GRM188R70J105KA01D)
C98  ValueDisplayed: 1µF  [0603]  (hidden comment: GRM188R70J105KA01D)
C99  ValueDisplayed: 1µF  [0603]  (hidden comment: GRM188R70J105KA01D)
C100  ValueDisplayed: 1µF  [0603]  (hidden comment: GRM188R70J105KA01D)
C101  ValueDisplayed: 1µF  [0603]  (hidden comment: GRM188R70J105KA01D)
C102  ValueDisplayed: 1µF  [0603]  (hidden comment: GRM188R70J105KA01D)
C103  ValueDisplayed: 1µF  [0603]  (hidden comment: GRM188R70J105KA01D)
C104  ValueDisplayed: 10µF  [0805_HV]  (hidden comment: GRM21BF50J106ZE01L)
C105  ValueDisplayed: 10µF  [0805_HV]  (hidden comment: GRM21BF50J106ZE01L)
C106  ValueDisplayed: 10µF  [0805_HV]  (hidden comment: GRM21BF50J106ZE01L)
C107  ValueDisplayed: 10µF  [0805_HV]  (hidden comment: GRM21BF50J106ZE01L)
C108  ValueDisplayed: 10µF  [0805_HV]  (hidden comment: GRM21BF50J106ZE01L)
C109  ValueDisplayed: 10µF  [0805_HV]  (hidden comment: GRM21BF50J106ZE01L)
C110  ValueDisplayed: 10µF  [0805_HV]  (hidden comment: GRM21BF50J106ZE01L)
C111  ValueDisplayed: 10µF  [0805_HV]  (hidden comment: GRM21BF50J106ZE01L)
C112  ValueDisplayed: 100µF  [TPE_D2E]  (hidden comment: 6TPE100MI)
C113  ValueDisplayed: 100µF  [TPE_D2E]  (hidden comment: 6TPE100MI)
C114  ValueDisplayed: 100µF  [TPE_D2E]  (hidden comment: 6TPE100MI)
C115  ValueDisplayed: 100µF  [TPE_D2E]  (hidden comment: 6TPE100MI)
C116  ValueDisplayed: 470µF  [TPF_D4]  (hidden comment: 6TPF470MAH)
C117  ValueDisplayed: 470µF  [TPF_D4]  (hidden comment: 6TPF470MAH)
C118  ValueDisplayed: 470µF  [TPF_D4]  (hidden comment: 6TPF470MAH)
C119  ValueDisplayed: 470µF  [TPF_D4]  (hidden comment: 6TPF470MAH)
C120  ValueDisplayed: 22µF  [0805_HV]  (hidden comment: GRM21BC80G226ME39L)
C121  ValueDisplayed: 22µF  [0805_HV]  (hidden comment: GRM21BC80G226ME39L)
C122  ValueDisplayed: 22µF  [0805_HV]  (hidden comment: GRM21BC80G226ME39L)
C123  ValueDisplayed: 22µF  [0805_HV]  (hidden comment: GRM21BC80G226ME39L)
C124  ValueDisplayed: 22µF  [0805_HV]  (hidden comment: GRM21BC80G226ME39L)
C125  ValueDisplayed: 47µF  [0805_HV]  (hidden comment: GRM21BR60J476ME15L)
C126  ValueDisplayed: 47µF  [0805_HV]  (hidden comment: GRM21BR60J476ME15L)
C127  ValueDisplayed: 47µF  [0805_HV]  (hidden comment: GRM21BR60J476ME15L)
C128  ValueDisplayed: 47µF  [0805_HV]  (hidden comment: GRM21BR60J476ME15L)
C129  ValueDisplayed: 47µF  [0805_HV]  (hidden comment: GRM21BR60J476ME15L)
R25  ValueDisplayed: 4.75k  [0402]  (hidden comment: CRCW04024K75FKED)
R26  ValueDisplayed: 4.75k  [0402]  (hidden comment: CRCW04024K75FKED)
R27  ValueDisplayed: 4.75k  [0402]  (hidden comment: CRCW04024K75FKED)
R28  ValueDisplayed: 4.75k  [0402]  (hidden comment: CRCW04024K75FKED)
R29  ValueDisplayed: 4.75k  [0402]  (hidden comment: CRCW04024K75FKED)
R30  ValueDisplayed: 4.75k  [0402]  (hidden comment: CRCW04024K75FKED)
U1  TCI6630K2L  [BGA900C80P30X30_2500X2500X355]  (parts B,K of 24)

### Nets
GND: C13.2 C14.2 C15.2 C16.2 C17.2 C18.2 C19.2 C20.2 C21.2 C22.2 C23.2 C24.2 C25.2 C26.2 C27.2 C28.2 C29.2 C30.2 C31.2 C32.2 C33.2 C34.2 C35.2 C36.2 C37.2 C38.2 C39.2 C40.2 C41.2 C42.2 C43.2 C44.2 C45.2 C46.2 C47.2 C48.2 C49.2 C50.2 C51.2 C52.2 C53.2 C54.2 C55.2 C56.2 C57.2 C58.2 C59.2 C60.2 C61.2 C62.2 C63.2 C64.2 C65.2 C66.2 C67.2 C68.2 C69.2 C70.2 C71.2 C72.2 C73.2 C74.2 C75.2 C76.2 C77.2 C78.2 C79.2 C80.2 C81.2 C82.2 C83.2 C84.2 C85.2 C86.2 C87.2 C88.2 C89.2 C90.2 C91.2 C92.2 C93.2 C94.2 C95.2 C96.2 C97.2 C98.2 C99.2 C100.2 C101.2 C102.2 C103.2 C104.2 C105.2 C106.2 C107.2 C108.2 C109.2 C110.2 C111.2 C112.2(-) C113.2(-) C114.2(-) C115.2(-) C116.2(-) C117.2(-) C118.2(-) C119.2(-) C120.2 C121.2 C122.2 C123.2 C124.2 C125.2 C126.2 C127.2 C128.2 C129.2  [project net DAC_OUT0N_T1]
VK2L_CVDD: C13.1 C14.1 C15.1 C16.1 C17.1 C18.1 C19.1 C20.1 C21.1 C22.1 C23.1 C24.1 C25.1 C26.1 C27.1 C28.1 C29.1 C30.1 C31.1 C32.1 C33.1 C34.1 C35.1 C36.1 C37.1 C38.1 C39.1 C40.1 C41.1 C42.1 C43.1 C44.1 C45.1 C46.1 C47.1 C48.1 C49.1 C50.1 C51.1 C52.1 C53.1 C54.1 C55.1 C56.1 C57.1 C58.1 C59.1 C60.1 C61.1 C62.1 C63.1 C64.1 C65.1 C66.1 C67.1 C68.1 C69.1 C70.1 C71.1 C72.1 C73.1 C74.1 C75.1 C76.1 C77.1 C78.1 C79.1 C80.1 C81.1 C82.1 C83.1 C84.1 C85.1 C86.1 C87.1 C88.1 C89.1 C90.1 C91.1 C92.1 C93.1 C94.1 C95.1 C96.1 C97.1 C98.1 C99.1 C100.1 C101.1 C102.1 C103.1 C104.1 C105.1 C106.1 C107.1 C108.1 C109.1 C110.1 C111.1 C112.1(+) C113.1(+) C114.1(+) C115.1(+) C116.1(+) C117.1(+) C118.1(+) C119.1(+) C120.1 C121.1 C122.1 C123.1 C124.1 C125.1 C126.1 C127.1 C128.1 C129.1 U1.AA9(CVDD) U1.AA11(CVDD) U1.AA13(CVDD) U1.AA15(CVDD) U1.AA17(CVDD) U1.AA19(CVDD) U1.AA21(CVDD) U1.AB10(CVDD) U1.AB12(CVDD) U1.AB20(CVDD) U1.AB22(CVDD) U1.K12(CVDD) U1.K14(CVDD) U1.K16(CVDD) U1.K18(CVDD) U1.K20(CVDD) U1.K22(CVDD) U1.L9(CVDD) U1.L11(CVDD) U1.L13(CVDD) U1.L15(CVDD) U1.L17(CVDD) U1.L19(CVDD) U1.L21(CVDD) U1.M14(CVDD) U1.M18(CVDD) U1.M20(CVDD) U1.M22(CVDD) U1.N9(CVDD) U1.N13(CVDD) U1.N17(CVDD) U1.P10(CVDD) U1.P12(CVDD) U1.P14(CVDD) U1.P18(CVDD) U1.P22(CVDD) U1.R11(CVDD) U1.R13(CVDD) U1.R15(CVDD) U1.R17(CVDD) U1.R19(CVDD) U1.R21(CVDD) U1.T12(CVDD) U1.T14(CVDD) U1.T16(CVDD) U1.T18(CVDD) U1.T20(CVDD) U1.T22(CVDD) U1.U11(CVDD) U1.U13(CVDD) U1.U15(CVDD) U1.U17(CVDD) U1.U19(CVDD) U1.U21(CVDD) U1.V12(CVDD) U1.V14(CVDD) U1.V16(CVDD) U1.V18(CVDD) U1.V20(CVDD) U1.V22(CVDD) U1.W9(CVDD) U1.W11(CVDD) U1.W13(CVDD) U1.W17(CVDD) U1.W19(CVDD) U1.W21(CVDD) U1.Y10(CVDD) U1.Y12(CVDD) U1.Y18(CVDD) U1.Y20(CVDD) U1.Y22(CVDD)
VSYS_1V8: R25.2 R26.2 R27.2 R28.2 R29.2 R30.2
K2L_VCNTL0: R30.1 U1.AJ27(VCNTL0) ; off-sheet K2L_VCNTL0
K2L_VCNTL1: R29.1 U1.AK28(VCNTL1) ; off-sheet K2L_VCNTL1
K2L_VCNTL2: R28.1 U1.AJ28(VCNTL2) ; off-sheet K2L_VCNTL2
K2L_VCNTL3: R27.1 U1.AG27(VCNTL3) ; off-sheet K2L_VCNTL3
K2L_VCNTL4_VCL: R26.1 U1.AH27(VCNTL4_VCL) ; off-sheet K2L_VCNTL4_VCL
K2L_VCNTL5_VD: R25.1 U1.AH26(VCNTL5_VD) ; off-sheet K2L_VCNTL5_VD
K2L_VDDCMON: U1.K10(VDDCMON) ; off-sheet K2L_VDDCMON
K2L_VDDTMON: U1.N23(VDDTMON)
K2L_VSSCMON: U1.K9(VSSCMON) ; off-sheet K2L_VSSCMON
K2L_VSSTMON: U1.M23(VSSTMON)

Not connected (* = marked no-connect by the designer): U1 H25(RSV012)* J25(RSV011)* W5(RSV010)* Y4(RSV009)*

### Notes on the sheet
- K2L CVDD CorePower Supply Pins and Decoupling
- 20 caps
- 0201 caps place directly under BGA
- 71 CVDD pins
- Recommend PDN layout simulation to select exact capacitor value in given location and package type.
- 11 caps
- VDDC/VSSCMON CVDD feedback signals routed to TPS544x regulator feedback pins
- 10 caps
- Place larger package caps as close to BGA as possible
- VCNTL signals routed to TPS544x regulator for Smart-Reflex control of CVDD voltage

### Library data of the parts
C13-C32 = GRM033R70J103KA01D: CAP, CERM, 0.01 µF, 6.3 V, +/- 10%, X7R, 0201; Manufacturer: MuRata; Polarized: N; CompType: Capacitor; Value: 0.01uF; U/M: EA; Cap_F: 0.00000001; Tolerance_%: 10; Value1: Unknown; VDC_V: 6.3; Value2: 6.3V; TaMin_C: -55; TaMax_C: 125; SizeArea_mm2: 0.18; SizeAreaWB_mm2: 2.08; SizeX_mm: 0.6; SizeY_mm: 0.3; SizeZ_mm: 0.26; AEC Category: Q200
C33-C52 = GRM033R60J223KE01D: CAP, CERM, 0.022 µF, 6.3 V, +/- 10%, X5R, 0201; Manufacturer: MuRata; Polarized: N; CompType: Capacitor; Value: 0.022uF; U/M: EA; Cap_F: 0.000000022; Tolerance_%: 10; Value1: Unknown; VDC_V: 6.3; Value2: 6.3V; TaMin_C: -55; TaMax_C: 85; SizeArea_mm2: 0.18; SizeAreaWB_mm2: 2.08; SizeX_mm: 0.6; SizeY_mm: 0.3; SizeZ_mm: 0.26; AEC Category: Q200
C53-C63 = GRM033R60J473KE19D: CAP, CERM, 0.047 µF, 6.3 V, +/- 10%, X5R, 0201; Manufacturer: MuRata; Polarized: N; CompType: Capacitor; Value: 0.047uF; U/M: EA; Cap_F: 0.000000047; Tolerance_%: 10; Value1: Unknown; VDC_V: 6.3; Value2: 6.3V; TaMin_C: -55; TaMax_C: 85; SizeArea_mm2: 0.18; SizeAreaWB_mm2: 2.08; SizeX_mm: 0.6; SizeY_mm: 0.3; SizeZ_mm: 0.26; AEC Category: Q200
C64-C73 = GRM033R60J104KE19D: CAP, CERM, 0.1 µF, 6.3 V, +/- 10%, X5R, 0201; Manufacturer: MuRata; Polarized: N; CompType: Capacitor; Value: 0.1uF; U/M: EA; Cap_F: 0.0000001; Tolerance_%: 10; Value1: Unknown; VDC_V: 6.3; Value2: 6.3V; TaMin_C: -55; TaMax_C: 85; Cap_Case: 0201; SizeArea_mm2: 0.18; SizeAreaWB_mm2: 2.08; SizeX_mm: 0.6; SizeY_mm: 0.3; SizeZ_mm: 0.33; AEC Category: Q200
C74-C83 = GRM188R61A224KA01D: CAP, CERM, 0.22 µF, 10 V, +/- 10%, X5R, 0603; Manufacturer: MuRata; Polarized: N; CompType: Capacitor; Value: 0.22uF; U/M: EA; Cap_F: 0.00000022; Tolerance_%: 10; Value1: Unknown; Value2: 10V; TaMin_C: -55; TaMax_C: 85; SizeArea_mm2: 1.28; SizeAreaWB_mm2: 4.68; SizeX_mm: 1.6; SizeY_mm: 0.8; SizeZ_mm: 1; AEC Category: Q200
C84-C93 = GRM188R61A474KA61D: CAP, CERM, 0.47 µF, 10 V, +/- 10%, X5R, 0603; Manufacturer: MuRata; Polarized: N; CompType: Capacitor; Value: 0.47uF; U/M: EA; Cap_F: 0.00000047; Tolerance_%: 10; Value1: Unknown; Value2: 10V; TaMin_C: -55; TaMax_C: 85; SizeArea_mm2: 1.28; SizeAreaWB_mm2: 4.68; SizeX_mm: 1.6; SizeY_mm: 0.8; SizeZ_mm: 1; AEC Category: Q200
C94-C103 = GRM188R70J105KA01D: CAP, CERM, 1 µF, 6.3 V, +/- 10%, X7R, 0603; Manufacturer: MuRata; Polarized: N; CompType: Capacitor; Value: 1uF; U/M: EA; Cap_F: 0.000001; Tolerance_%: 10; Value1: Unknown; VDC_V: 6.3; Value2: 6.3V; TaMin_C: -55; TaMax_C: 125; SizeArea_mm2: 1.28; SizeAreaWB_mm2: 4.68; SizeX_mm: 1.6; SizeY_mm: 0.8; SizeZ_mm: 1; AEC Category: Q200
C104-C111 = GRM21BF50J106ZE01L: CAP, CERM, 10 µF, 6.3 V, +80/-20%, Y5V, 0805; Manufacturer: MuRata; Polarized: N; CompType: Capacitor; Value: 10uF; U/M: EA; Cap_F: 0.00001; Tolerance_%: 80; ESR_ohm: 0.1; Value1: 0.1 ohm; VDC_V: 6.3; Value2: 6.3V; TaMin_C: -30; TaMax_C: 85; Cap_Case: 0805; SizeArea_mm2: 2.5; SizeAreaWB_mm2: 6.75; SizeX_mm: 2; SizeY_mm: 1.25; SizeZ_mm: 1.45; AEC Category: Q200
C112-C115 = 6TPE100MI: CAP, TA, 100 µF, 6.3 V, +/- 20%, 0.018 ohm, SMD; Manufacturer: Panasonic; Polarized: Y; CompType: Capacitor; Value: 100uF; U/M: EA; Cap_F: 0.0001; Tolerance_%: 20; VDC_V: 6.3; Value2: 6.3V; ESR_ohm: 0.018; IRMS_A: 2.8; TaMin_C: -55; TaMax_C: 105; Cap_Case: D
C116-C119 = 6TPF470MAH: CAP, TA, 470 µF, 6.3 V, +/- 20%, 0.01 ohm, SMD; Manufacturer: Panasonic; Polarized: Y; CompType: Capacitor; Value: 470uF; U/M: EA; Cap_F: 0.00047; Tolerance_%: 20; VDC_V: 6.3; Value2: 6.3V; ESR_ohm: 0.01; IRMS_A: 4.4; TaMin_C: -55; TaMax_C: 105; Cap_Case: D4
C120-C124 = GRM21BC80G226ME39L: CAP, CERM, 22 µF, 4 V, +/- 20%, X6S, 0805; Manufacturer: MuRata; Polarized: N; CompType: Capacitor; Value: 22uF; U/M: EA; Cap_F: 0.000022; Tolerance_%: 20; Value1: Unknown; VDC_V: 4; Value2: 4V; TaMin_C: -55; TaMax_C: 105; Cap_Case: 0805; SizeArea_mm2: 2.5; SizeAreaWB_mm2: 6.75; SizeX_mm: 2; SizeY_mm: 1.25; SizeZ_mm: 1.45; AEC Category: Q200
C125-C129 = GRM21BR60J476ME15L: CAP, CERM, 47 µF, 6.3 V, +/- 20%, X5R, 0805; Manufacturer: MuRata; Polarized: N; CompType: Capacitor; Value: 47uF; U/M: EA; Cap_F: 0.000047; Tolerance_%: 20; Value1: Unknown; VDC_V: 6.3; Value2: 6.3V; TaMin_C: -55; TaMax_C: 85; Cap_Case: 0805; SizeArea_mm2: 2.5; SizeAreaWB_mm2: 6.75; SizeX_mm: 2; SizeY_mm: 1.25; SizeZ_mm: 1.45; AEC Category: Q200
R25-R30 = CRCW04024K75FKED: RES, 4.75 k, 1%, 0.063 W, 0402; Manufacturer: Vishay-Dale; CompType: Resistor; Value: 4.75k; Res_ohm: 4750; Value_Code: 4k75; Tolerance_%: 1; Power_W: 0.063; Value2: 0.063W; VDC_V: 50; TempCo: 100 ppm/C; EIA_Code: E96; U/M: EA
U1 = lamarr_soc_TCI6630K2L: as U1 on sheet k2l_soc_01

## Sheet k2l_soc_03.SchDoc
size 431 x 279 mm; Date: Not shown in title block; ApprovedBy: Not shown in title block; CheckedBy: Not shown in title block; Author: Not shown in title block; CompanyName: Not shown in title block; Engineer: Not shown in title block; Organization: Not shown in title block; Address1: Not shown in title block; Address2: Not shown in title block; Address3: Not shown in title block; Address4: Not shown in title block; DocumentNumber: 7; Revision: Use project parameter SCH_Rev; SheetNumber: 7; SheetTotal: 38; PageSetup: Record=PageOptions¦CenterHorizontal=True¦CenterVertical=True¦PrintScale=1.00¦XCorrection=1.00¦YCorrection=1.00¦PrintKind=0¦BorderSize=5000000¦LeftOffset=0¦BottomOffset=0¦Orientation=2¦PaperLength=1000¦PaperWidth=1000¦Scale=100¦PaperSource=15¦PrintQuality=600¦MediaType=1¦DitherType=10¦PaperKind=Letter¦PrintScaleMode=1
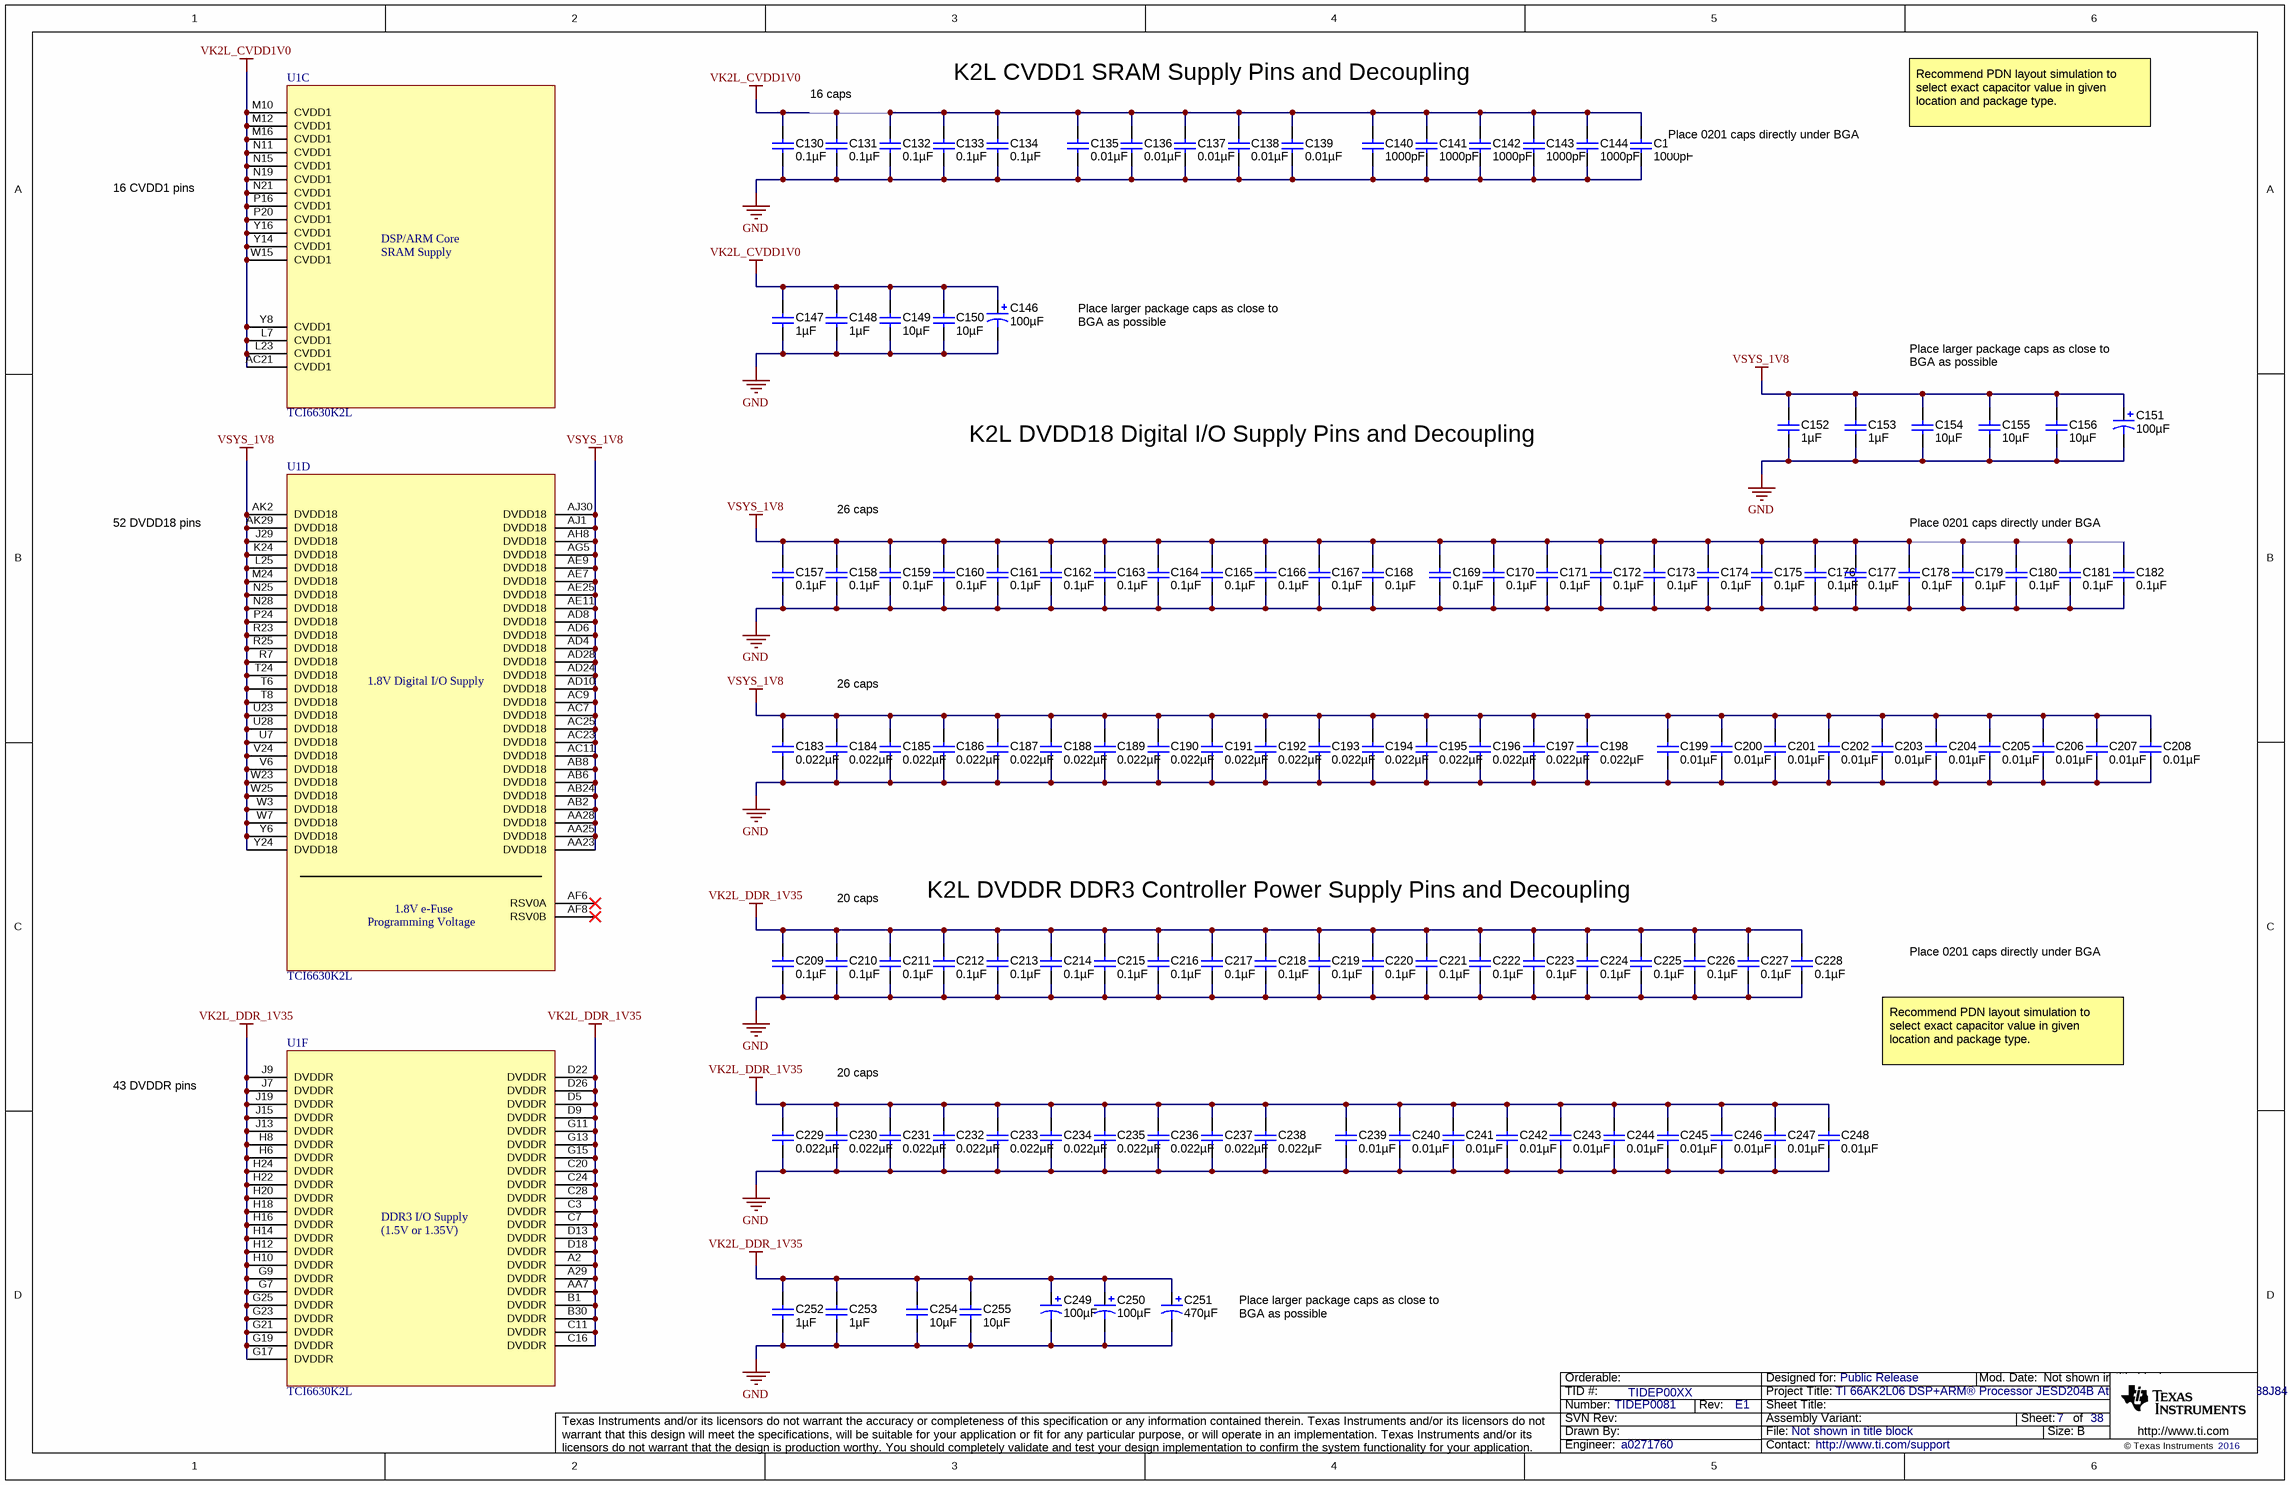
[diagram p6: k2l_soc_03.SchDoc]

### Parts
C130  ValueDisplayed: 0.1µF  [0201_033]  (hidden comment: GRM033R60J104KE19D)
C131  ValueDisplayed: 0.1µF  [0201_033]  (hidden comment: GRM033R60J104KE19D)
C132  ValueDisplayed: 0.1µF  [0201_033]  (hidden comment: GRM033R60J104KE19D)
C133  ValueDisplayed: 0.1µF  [0201_033]  (hidden comment: GRM033R60J104KE19D)
C134  ValueDisplayed: 0.1µF  [0201_033]  (hidden comment: GRM033R60J104KE19D)
C135  ValueDisplayed: 0.01µF  [0201]  (hidden comment: GRM033R60J103KA01D)
C136  ValueDisplayed: 0.01µF  [0201]  (hidden comment: GRM033R60J103KA01D)
C137  ValueDisplayed: 0.01µF  [0201]  (hidden comment: GRM033R60J103KA01D)
C138  ValueDisplayed: 0.01µF  [0201]  (hidden comment: GRM033R60J103KA01D)
C139  ValueDisplayed: 0.01µF  [0201]  (hidden comment: GRM033R60J103KA01D)
C140  ValueDisplayed: 1000pF  [0201]  (hidden comment: GRM033R71C102KA01D)
C141  ValueDisplayed: 1000pF  [0201]  (hidden comment: GRM033R71C102KA01D)
C142  ValueDisplayed: 1000pF  [0201]  (hidden comment: GRM033R71C102KA01D)
C143  ValueDisplayed: 1000pF  [0201]  (hidden comment: GRM033R71C102KA01D)
C144  ValueDisplayed: 1000pF  [0201]  (hidden comment: GRM033R71C102KA01D)
C145  ValueDisplayed: 1000pF  [0201]  (hidden comment: GRM033R71C102KA01D)
C146  ValueDisplayed: 100µF  [TPE_D2E]  (hidden comment: 6TPE100MI)
C147  ValueDisplayed: 1µF  [0603]  (hidden comment: GRM188R70J105KA01D)
C148  ValueDisplayed: 1µF  [0603]  (hidden comment: GRM188R70J105KA01D)
C149  ValueDisplayed: 10µF  [0805_HV]  (hidden comment: GRM21BR70J106KE76L)
C150  ValueDisplayed: 10µF  [0805_HV]  (hidden comment: GRM21BR70J106KE76L)
C151  ValueDisplayed: 100µF  [TPE_D2E]  (hidden comment: 6TPE100MI)
C152  ValueDisplayed: 1µF  [0603]  (hidden comment: GRM188R70J105KA01D)
C153  ValueDisplayed: 1µF  [0603]  (hidden comment: GRM188R70J105KA01D)
C154  ValueDisplayed: 10µF  [0805_HV]  (hidden comment: GRM21BR70J106KE76L)
C155  ValueDisplayed: 10µF  [0805_HV]  (hidden comment: GRM21BR70J106KE76L)
C156  ValueDisplayed: 10µF  [0805_HV]  (hidden comment: GRM21BR70J106KE76L)
C157  ValueDisplayed: 0.1µF  [0201_033]  (hidden comment: GRM033R60J104KE19D)
C158  ValueDisplayed: 0.1µF  [0201_033]  (hidden comment: GRM033R60J104KE19D)
C159  ValueDisplayed: 0.1µF  [0201_033]  (hidden comment: GRM033R60J104KE19D)
C160  ValueDisplayed: 0.1µF  [0201_033]  (hidden comment: GRM033R60J104KE19D)
C161  ValueDisplayed: 0.1µF  [0201_033]  (hidden comment: GRM033R60J104KE19D)
C162  ValueDisplayed: 0.1µF  [0201_033]  (hidden comment: GRM033R60J104KE19D)
C163  ValueDisplayed: 0.1µF  [0201_033]  (hidden comment: GRM033R60J104KE19D)
C164  ValueDisplayed: 0.1µF  [0201_033]  (hidden comment: GRM033R60J104KE19D)
C165  ValueDisplayed: 0.1µF  [0201_033]  (hidden comment: GRM033R60J104KE19D)
C166  ValueDisplayed: 0.1µF  [0201_033]  (hidden comment: GRM033R60J104KE19D)
C167  ValueDisplayed: 0.1µF  [0201_033]  (hidden comment: GRM033R60J104KE19D)
C168  ValueDisplayed: 0.1µF  [0201_033]  (hidden comment: GRM033R60J104KE19D)
C169  ValueDisplayed: 0.1µF  [0201_033]  (hidden comment: GRM033R60J104KE19D)
C170  ValueDisplayed: 0.1µF  [0201_033]  (hidden comment: GRM033R60J104KE19D)
C171  ValueDisplayed: 0.1µF  [0201_033]  (hidden comment: GRM033R60J104KE19D)
C172  ValueDisplayed: 0.1µF  [0201_033]  (hidden comment: GRM033R60J104KE19D)
C173  ValueDisplayed: 0.1µF  [0201_033]  (hidden comment: GRM033R60J104KE19D)
C174  ValueDisplayed: 0.1µF  [0201_033]  (hidden comment: GRM033R60J104KE19D)
C175  ValueDisplayed: 0.1µF  [0201_033]  (hidden comment: GRM033R60J104KE19D)
C176  ValueDisplayed: 0.1µF  [0201_033]  (hidden comment: GRM033R60J104KE19D)
C177  ValueDisplayed: 0.1µF  [0201_033]  (hidden comment: GRM033R60J104KE19D)
C178  ValueDisplayed: 0.1µF  [0201_033]  (hidden comment: GRM033R60J104KE19D)
C179  ValueDisplayed: 0.1µF  [0201_033]  (hidden comment: GRM033R60J104KE19D)
C180  ValueDisplayed: 0.1µF  [0201_033]  (hidden comment: GRM033R60J104KE19D)
C181  ValueDisplayed: 0.1µF  [0201_033]  (hidden comment: GRM033R60J104KE19D)
C182  ValueDisplayed: 0.1µF  [0201_033]  (hidden comment: GRM033R60J104KE19D)
C183  ValueDisplayed: 0.022µF  [0201]  (hidden comment: GRM033C80G223KE01D)
C184  ValueDisplayed: 0.022µF  [0201]  (hidden comment: GRM033C80G223KE01D)
C185  ValueDisplayed: 0.022µF  [0201]  (hidden comment: GRM033C80G223KE01D)
C186  ValueDisplayed: 0.022µF  [0201]  (hidden comment: GRM033C80G223KE01D)
C187  ValueDisplayed: 0.022µF  [0201]  (hidden comment: GRM033C80G223KE01D)
C188  ValueDisplayed: 0.022µF  [0201]  (hidden comment: GRM033C80G223KE01D)
C189  ValueDisplayed: 0.022µF  [0201]  (hidden comment: GRM033C80G223KE01D)
C190  ValueDisplayed: 0.022µF  [0201]  (hidden comment: GRM033C80G223KE01D)
C191  ValueDisplayed: 0.022µF  [0201]  (hidden comment: GRM033C80G223KE01D)
C192  ValueDisplayed: 0.022µF  [0201]  (hidden comment: GRM033C80G223KE01D)
C193  ValueDisplayed: 0.022µF  [0201]  (hidden comment: GRM033C80G223KE01D)
C194  ValueDisplayed: 0.022µF  [0201]  (hidden comment: GRM033C80G223KE01D)
C195  ValueDisplayed: 0.022µF  [0201]  (hidden comment: GRM033C80G223KE01D)
C196  ValueDisplayed: 0.022µF  [0201]  (hidden comment: GRM033C80G223KE01D)
C197  ValueDisplayed: 0.022µF  [0201]  (hidden comment: GRM033C80G223KE01D)
C198  ValueDisplayed: 0.022µF  [0201]  (hidden comment: GRM033C80G223KE01D)
C199  ValueDisplayed: 0.01µF  [0201]  (hidden comment: GRM033R60J103KA01D)
C200  ValueDisplayed: 0.01µF  [0201]  (hidden comment: GRM033R60J103KA01D)
C201  ValueDisplayed: 0.01µF  [0201]  (hidden comment: GRM033R60J103KA01D)
C202  ValueDisplayed: 0.01µF  [0201]  (hidden comment: GRM033R60J103KA01D)
C203  ValueDisplayed: 0.01µF  [0201]  (hidden comment: GRM033R60J103KA01D)
C204  ValueDisplayed: 0.01µF  [0201]  (hidden comment: GRM033R60J103KA01D)
C205  ValueDisplayed: 0.01µF  [0201]  (hidden comment: GRM033R60J103KA01D)
C206  ValueDisplayed: 0.01µF  [0201]  (hidden comment: GRM033R60J103KA01D)
C207  ValueDisplayed: 0.01µF  [0201]  (hidden comment: GRM033R60J103KA01D)
C208  ValueDisplayed: 0.01µF  [0201]  (hidden comment: GRM033R60J103KA01D)
C209  ValueDisplayed: 0.1µF  [0201_033]  (hidden comment: GRM033R60J104KE19D)
C210  ValueDisplayed: 0.1µF  [0201_033]  (hidden comment: GRM033R60J104KE19D)
C211  ValueDisplayed: 0.1µF  [0201_033]  (hidden comment: GRM033R60J104KE19D)
C212  ValueDisplayed: 0.1µF  [0201_033]  (hidden comment: GRM033R60J104KE19D)
C213  ValueDisplayed: 0.1µF  [0201_033]  (hidden comment: GRM033R60J104KE19D)
C214  ValueDisplayed: 0.1µF  [0201_033]  (hidden comment: GRM033R60J104KE19D)
C215  ValueDisplayed: 0.1µF  [0201_033]  (hidden comment: GRM033R60J104KE19D)
C216  ValueDisplayed: 0.1µF  [0201_033]  (hidden comment: GRM033R60J104KE19D)
C217  ValueDisplayed: 0.1µF  [0201_033]  (hidden comment: GRM033R60J104KE19D)
C218  ValueDisplayed: 0.1µF  [0201_033]  (hidden comment: GRM033R60J104KE19D)
C219  ValueDisplayed: 0.1µF  [0201_033]  (hidden comment: GRM033R60J104KE19D)
C220  ValueDisplayed: 0.1µF  [0201_033]  (hidden comment: GRM033R60J104KE19D)
C221  ValueDisplayed: 0.1µF  [0201_033]  (hidden comment: GRM033R60J104KE19D)
C222  ValueDisplayed: 0.1µF  [0201_033]  (hidden comment: GRM033R60J104KE19D)
C223  ValueDisplayed: 0.1µF  [0201_033]  (hidden comment: GRM033R60J104KE19D)
C224  ValueDisplayed: 0.1µF  [0201_033]  (hidden comment: GRM033R60J104KE19D)
C225  ValueDisplayed: 0.1µF  [0201_033]  (hidden comment: GRM033R60J104KE19D)
C226  ValueDisplayed: 0.1µF  [0201_033]  (hidden comment: GRM033R60J104KE19D)
C227  ValueDisplayed: 0.1µF  [0201_033]  (hidden comment: GRM033R60J104KE19D)
C228  ValueDisplayed: 0.1µF  [0201_033]  (hidden comment: GRM033R60J104KE19D)
C229  ValueDisplayed: 0.022µF  [0201]  (hidden comment: GRM033C80G223KE01D)
C230  ValueDisplayed: 0.022µF  [0201]  (hidden comment: GRM033C80G223KE01D)
C231  ValueDisplayed: 0.022µF  [0201]  (hidden comment: GRM033C80G223KE01D)
C232  ValueDisplayed: 0.022µF  [0201]  (hidden comment: GRM033C80G223KE01D)
C233  ValueDisplayed: 0.022µF  [0201]  (hidden comment: GRM033C80G223KE01D)
C234  ValueDisplayed: 0.022µF  [0201]  (hidden comment: GRM033C80G223KE01D)
C235  ValueDisplayed: 0.022µF  [0201]  (hidden comment: GRM033C80G223KE01D)
C236  ValueDisplayed: 0.022µF  [0201]  (hidden comment: GRM033C80G223KE01D)
C237  ValueDisplayed: 0.022µF  [0201]  (hidden comment: GRM033C80G223KE01D)
C238  ValueDisplayed: 0.022µF  [0201]  (hidden comment: GRM033C80G223KE01D)
C239  ValueDisplayed: 0.01µF  [0201]  (hidden comment: GRM033R60J103KA01D)
C240  ValueDisplayed: 0.01µF  [0201]  (hidden comment: GRM033R60J103KA01D)
C241  ValueDisplayed: 0.01µF  [0201]  (hidden comment: GRM033R60J103KA01D)
C242  ValueDisplayed: 0.01µF  [0201]  (hidden comment: GRM033R60J103KA01D)
C243  ValueDisplayed: 0.01µF  [0201]  (hidden comment: GRM033R60J103KA01D)
C244  ValueDisplayed: 0.01µF  [0201]  (hidden comment: GRM033R60J103KA01D)
C245  ValueDisplayed: 0.01µF  [0201]  (hidden comment: GRM033R60J103KA01D)
C246  ValueDisplayed: 0.01µF  [0201]  (hidden comment: GRM033R60J103KA01D)
C247  ValueDisplayed: 0.01µF  [0201]  (hidden comment: GRM033R60J103KA01D)
C248  ValueDisplayed: 0.01µF  [0201]  (hidden comment: GRM033R60J103KA01D)
C249  ValueDisplayed: 100µF  [TPE_D2E]  (hidden comment: 6TPE100MI)
C250  ValueDisplayed: 100µF  [TPE_D2E]  (hidden comment: 6TPE100MI)
C251  ValueDisplayed: 470µF  [TPF_D4]  (hidden comment: 6TPF470MAH)
C252  ValueDisplayed: 1µF  [0603]  (hidden comment: GRM188R70J105KA01D)
C253  ValueDisplayed: 1µF  [0603]  (hidden comment: GRM188R70J105KA01D)
C254  ValueDisplayed: 10µF  [0805_HV]  (hidden comment: GRM21BR70J106KE76L)
C255  ValueDisplayed: 10µF  [0805_HV]  (hidden comment: GRM21BR70J106KE76L)
U1  TCI6630K2L  [BGA900C80P30X30_2500X2500X355]  (parts C,D,F of 24)

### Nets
GND: C130.2 C131.2 C132.2 C133.2 C134.2 C135.2 C136.2 C137.2 C138.2 C139.2 C140.2 C141.2 C142.2 C143.2 C144.2 C145.2 C146.2(-) C147.2 C148.2 C149.2 C150.2 C151.2(-) C152.2 C153.2 C154.2 C155.2 C156.2 C157.2 C158.2 C159.2 C160.2 C161.2 C162.2 C163.2 C164.2 C165.2 C166.2 C167.2 C168.2 C169.2 C170.2 C171.2 C172.2 C173.2 C174.2 C175.2 C176.2 C177.2 C178.2 C179.2 C180.2 C181.2 C182.2 C183.2 C184.2 C185.2 C186.2 C187.2 C188.2 C189.2 C190.2 C191.2 C192.2 C193.2 C194.2 C195.2 C196.2 C197.2 C198.2 C199.2 C200.2 C201.2 C202.2 C203.2 C204.2 C205.2 C206.2 C207.2 C208.2 C209.2 C210.2 C211.2 C212.2 C213.2 C214.2 C215.2 C216.2 C217.2 C218.2 C219.2 C220.2 C221.2 C222.2 C223.2 C224.2 C225.2 C226.2 C227.2 C228.2 C229.2 C230.2 C231.2 C232.2 C233.2 C234.2 C235.2 C236.2 C237.2 C238.2 C239.2 C240.2 C241.2 C242.2 C243.2 C244.2 C245.2 C246.2 C247.2 C248.2 C249.2(-) C250.2(-) C251.2(-) C252.2 C253.2 C254.2 C255.2  [project net DAC_OUT0N_T1]
VK2L_CVDD1V0: C130.1 C131.1 C132.1 C133.1 C134.1 C135.1 C136.1 C137.1 C138.1 C139.1 C140.1 C141.1 C142.1 C143.1 C144.1 C145.1 C146.1(+) C147.1 C148.1 C149.1 C150.1 U1.AC21(CVDD1) U1.L7(CVDD1) U1.L23(CVDD1) U1.M10(CVDD1) U1.M12(CVDD1) U1.M16(CVDD1) U1.N11(CVDD1) U1.N15(CVDD1) U1.N19(CVDD1) U1.N21(CVDD1) U1.P16(CVDD1) U1.P20(CVDD1) U1.W15(CVDD1) U1.Y8(CVDD1) U1.Y14(CVDD1) U1.Y16(CVDD1)
VK2L_DDR_1V35: C209.1 C210.1 C211.1 C212.1 C213.1 C214.1 C215.1 C216.1 C217.1 C218.1 C219.1 C220.1 C221.1 C222.1 C223.1 C224.1 C225.1 C226.1 C227.1 C228.1 C229.1 C230.1 C231.1 C232.1 C233.1 C234.1 C235.1 C236.1 C237.1 C238.1 C239.1 C240.1 C241.1 C242.1 C243.1 C244.1 C245.1 C246.1 C247.1 C248.1 C249.1(+) C250.1(+) C251.1(+) C252.1 C253.1 C254.1 C255.1 U1.A2(DVDDR) U1.A29(DVDDR) U1.AA7(DVDDR) U1.B1(DVDDR) U1.B30(DVDDR) U1.C3(DVDDR) U1.C7(DVDDR) U1.C11(DVDDR) U1.C16(DVDDR) U1.C20(DVDDR) U1.C24(DVDDR) U1.C28(DVDDR) U1.D5(DVDDR) U1.D9(DVDDR) U1.D13(DVDDR) U1.D18(DVDDR) U1.D22(DVDDR) U1.D26(DVDDR) U1.G7(DVDDR) U1.G9(DVDDR) U1.G11(DVDDR) U1.G13(DVDDR) U1.G15(DVDDR) U1.G17(DVDDR) U1.G19(DVDDR) U1.G21(DVDDR) U1.G23(DVDDR) U1.G25(DVDDR) U1.H6(DVDDR) U1.H8(DVDDR) U1.H10(DVDDR) U1.H12(DVDDR) U1.H14(DVDDR) U1.H16(DVDDR) U1.H18(DVDDR) U1.H20(DVDDR) U1.H22(DVDDR) U1.H24(DVDDR) U1.J7(DVDDR) U1.J9(DVDDR) U1.J13(DVDDR) U1.J15(DVDDR) U1.J19(DVDDR)
VSYS_1V8: C151.1(+) C152.1 C153.1 C154.1 C155.1 C156.1 C157.1 C158.1 C159.1 C160.1 C161.1 C162.1 C163.1 C164.1 C165.1 C166.1 C167.1 C168.1 C169.1 C170.1 C171.1 C172.1 C173.1 C174.1 C175.1 C176.1 C177.1 C178.1 C179.1 C180.1 C181.1 C182.1 C183.1 C184.1 C185.1 C186.1 C187.1 C188.1 C189.1 C190.1 C191.1 C192.1 C193.1 C194.1 C195.1 C196.1 C197.1 C198.1 C199.1 C200.1 C201.1 C202.1 C203.1 C204.1 C205.1 C206.1 C207.1 C208.1 U1.AA23(DVDD18) U1.AA25(DVDD18) U1.AA28(DVDD18) U1.AB2(DVDD18) U1.AB6(DVDD18) U1.AB8(DVDD18) U1.AB24(DVDD18) U1.AC7(DVDD18) U1.AC9(DVDD18) U1.AC11(DVDD18) U1.AC23(DVDD18) U1.AC25(DVDD18) U1.AD4(DVDD18) U1.AD6(DVDD18) U1.AD8(DVDD18) U1.AD10(DVDD18) U1.AD24(DVDD18) U1.AD28(DVDD18) U1.AE7(DVDD18) U1.AE9(DVDD18) U1.AE11(DVDD18) U1.AE25(DVDD18) U1.AG5(DVDD18) U1.AH8(DVDD18) U1.AJ1(DVDD18) U1.AJ30(DVDD18) U1.AK2(DVDD18) U1.AK29(DVDD18) U1.J29(DVDD18) U1.K24(DVDD18) U1.L25(DVDD18) U1.M24(DVDD18) U1.N25(DVDD18) U1.N28(DVDD18) U1.P24(DVDD18) U1.R7(DVDD18) U1.R23(DVDD18) U1.R25(DVDD18) U1.T6(DVDD18) U1.T8(DVDD18) U1.T24(DVDD18) U1.U7(DVDD18) U1.U23(DVDD18) U1.U28(DVDD18) U1.V6(DVDD18) U1.V24(DVDD18) U1.W3(DVDD18) U1.W7(DVDD18) U1.W23(DVDD18) U1.W25(DVDD18) U1.Y6(DVDD18) U1.Y24(DVDD18)

Not connected (* = marked no-connect by the designer): U1 AF6(RSV0A)* AF8(RSV0B)*

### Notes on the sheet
- K2L CVDD1 SRAM Supply Pins and Decoupling
- 16 caps
- (near C145) Place 0201 caps directly under BGA
- Recommend PDN layout simulation to select exact capacitor value in given location and package type.
- 16 CVDD1 pins
- Place larger package caps as close to BGA as possible
- K2L DVDD18 Digital I/O Supply Pins and Decoupling
- 52 DVDD18 pins
- 26 caps
- Place 0201 caps directly under BGA
- K2L DVDDR DDR3 Controller Power Supply Pins and Decoupling
- 20 caps
- 43 DVDDR pins

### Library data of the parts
C130-C134 C157-C182 C209-C228 = GRM033R60J104KE19D: as C64 on sheet k2l_soc_02
C135-C139 C199-C208 C239-C248 = GRM033R60J103KA01D: CAP, CERM, 0.01 µF, 6.3 V, +/- 10%, X5R, 0201; Manufacturer: MuRata; Polarized: N; CompType: Capacitor; Value: 0.01uF; U/M: EA; Cap_F: 0.00000001; Tolerance_%: 10; Value1: Unknown; VDC_V: 6.3; Value2: 6.3V; TaMin_C: -55; TaMax_C: 85; SizeArea_mm2: 0.18; SizeAreaWB_mm2: 2.08; SizeX_mm: 0.6; SizeY_mm: 0.3; SizeZ_mm: 0.26; AEC Category: Q200
C140-C145 = GRM033R71C102KA01D: CAP, CERM, 1000 pF, 16 V, +/- 10%, X7R, 0201; Manufacturer: MuRata; Polarized: N; CompType: Capacitor; Value: 1000pF; U/M: EA; Cap_F: 0.000000001; Tolerance_%: 10; Value1: Unknown; VDC_V: 16; Value2: 16V; TaMin_C: -55; TaMax_C: 125; SizeArea_mm2: 0.18; SizeAreaWB_mm2: 2.08; SizeX_mm: 0.6; SizeY_mm: 0.3; SizeZ_mm: 0.26; AEC Category: Q200
C146 C151 C249 C250 = 6TPE100MI: as C112 on sheet k2l_soc_02
C147 C148 C152 C153 C252 C253 = GRM188R70J105KA01D: as C94 on sheet k2l_soc_02
C149 C150 C154-C156 C254 C255 = GRM21BR70J106KE76L: CAP, CERM, 10 µF, 6.3 V, +/- 10%, X7R, 0805; Manufacturer: MuRata; Polarized: N; CompType: Capacitor; Value: 10uF; U/M: EA; Cap_F: 0.00001; Tolerance_%: 10; Value1: Unknown; VDC_V: 6.3; Value2: 6.3V; TaMin_C: -55; TaMax_C: 125; Cap_Case: 0805; SizeArea_mm2: 2.5; SizeAreaWB_mm2: 6.75; SizeX_mm: 2; SizeY_mm: 1.25; SizeZ_mm: 1.45; AEC Category: Q200
C183-C198 C229-C238 = GRM033C80G223KE01D: CAP, CERM, 0.022 µF, 4 V, +/- 10%, X6S, 0201; Manufacturer: MuRata; Polarized: N; CompType: Capacitor; Value: 0.022uF; U/M: EA; Cap_F: 0.000000022; Tolerance_%: 10; Value1: Unknown; VDC_V: 4; Value2: 4V; TaMin_C: -55; TaMax_C: 105; SizeArea_mm2: 0.18; SizeAreaWB_mm2: 2.08; SizeX_mm: 0.6; SizeY_mm: 0.3; SizeZ_mm: 0.26; AEC Category: Q200
C251 = 6TPF470MAH: as C116 on sheet k2l_soc_02
U1 = lamarr_soc_TCI6630K2L: as U1 on sheet k2l_soc_01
